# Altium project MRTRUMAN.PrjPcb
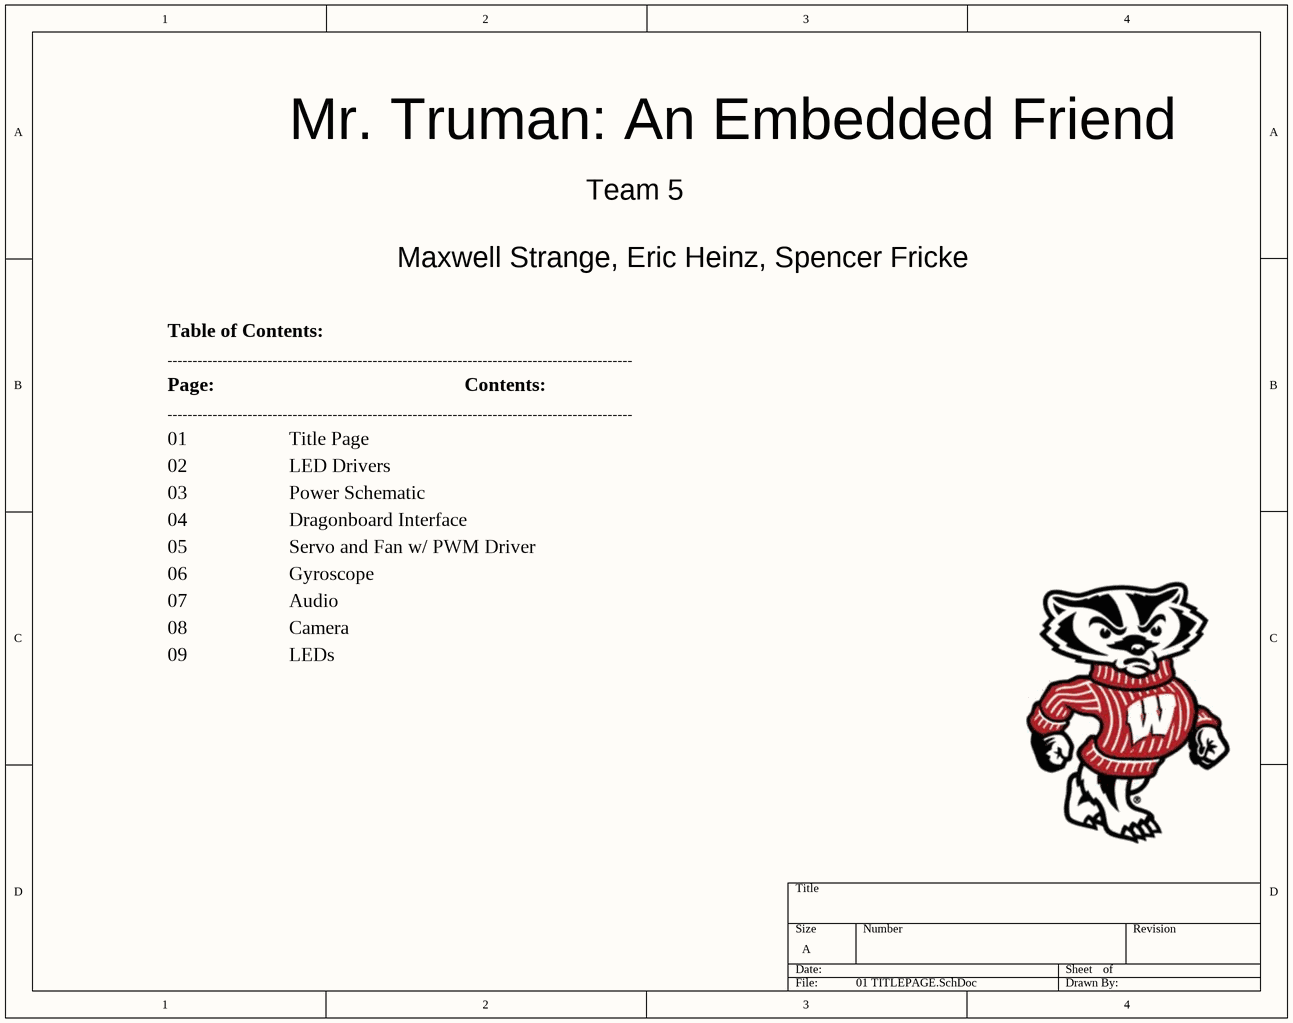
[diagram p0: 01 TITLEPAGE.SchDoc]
9 sheets, 246 parts. Net scope: global (net labels, ports and power ports of the same name join across sheets).
Sheets:
  01 TITLEPAGE.SchDoc
  02 LEDs.SchDoc
  03 POWER.SchDoc
  04 DragonBoard_INTF.SchDoc
  05 SERVO_FAN.SchDoc
  06 Gyro.SchDoc
  07 Audio.SchDoc
  08 Camera.SchDoc
  09 LEDs(2).SchDoc

## Sheet 01 TITLEPAGE.SchDoc: Mr. Truman ECE 453 Project
size A

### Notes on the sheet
- Mr. Truman: An Embedded Friend
- Team 5
- Maxwell Strange, Eric Heinz, Spencer Fricke
- Table of Contents:
- ---------------------------------------------------------------------------------------------
- Page:
- Contents:
- 01
- 02
- 03
- Title Page
- LED Drivers
- Power Schematic
- 04
- 05
- Dragonboard Interface
- Servo and Fan w/ PWM Driver
- 06
- 07
- 08
- Gyroscope
- Audio
- Camera
- 09
- LEDs

## Sheet 02 LEDs.SchDoc
size A
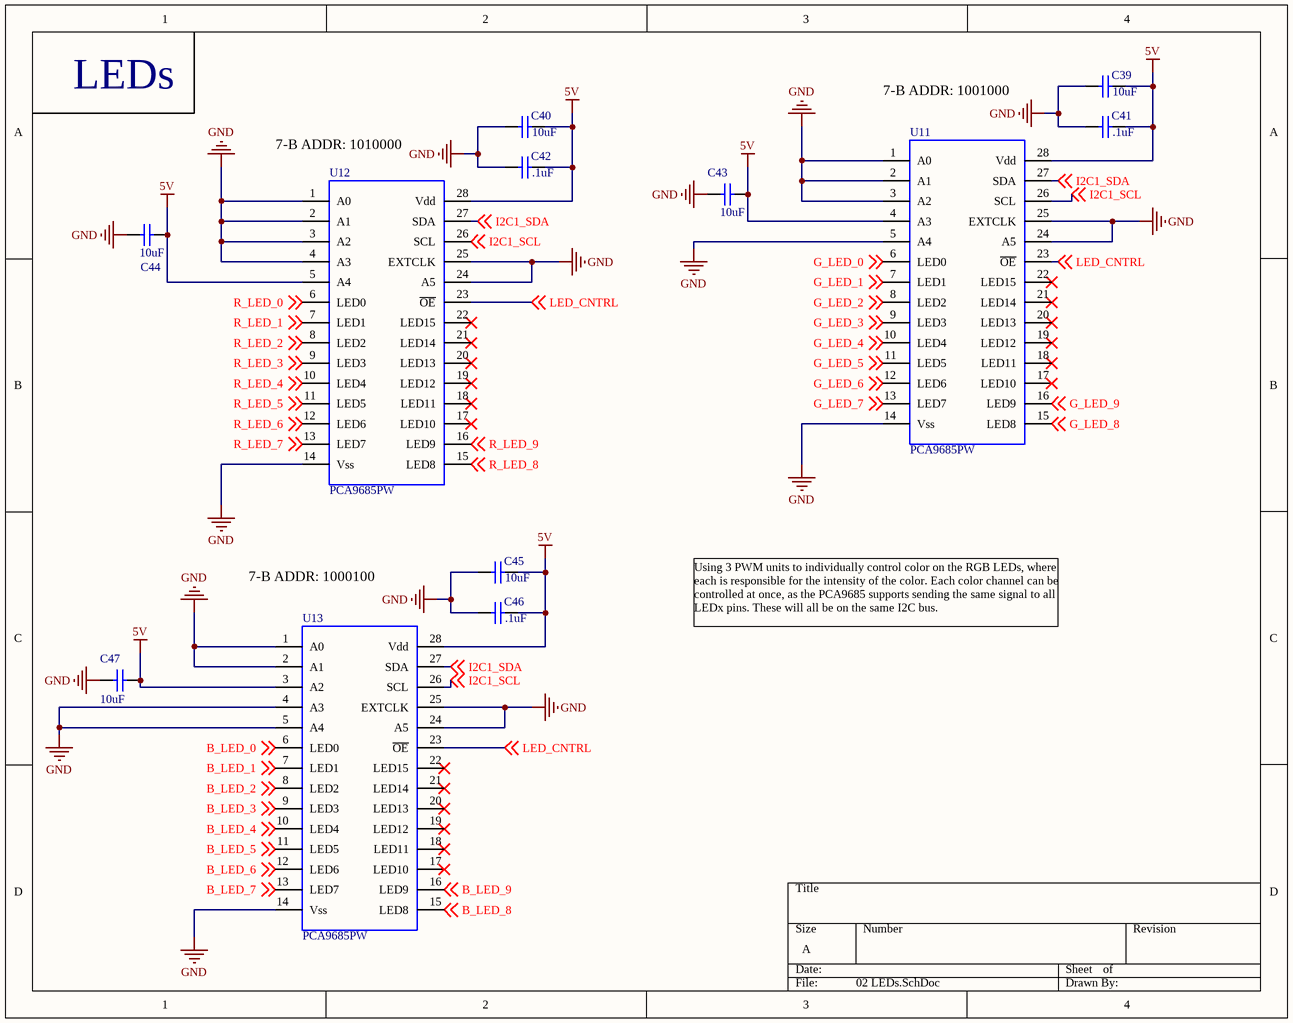
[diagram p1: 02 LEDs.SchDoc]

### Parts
C39  value 10uF  [CAPC2012X135N]  (hidden comment: CAP_0805_10u_16V)
C40  value 10uF  [CAPC2012X135N]  (hidden comment: CAP_0805_10u_16V)
C41  value .1uF  [CAPC2012X135N]  (hidden comment: CAP_0805_.1u_250V)
C42  value .1uF  [CAPC2012X135N]  (hidden comment: CAP_0805_.1u_250V)
C43  value 10uF  [CAPC2012X135N]  (hidden comment: CAP_0805_10u_16V)
C44  value 10uF  [CAPC2012X135N]  (hidden comment: CAP_0805_10u_16V)
C45  value 10uF  [CAPC2012X135N]  (hidden comment: CAP_0805_10u_16V)
C46  value .1uF  [CAPC2012X135N]  (hidden comment: CAP_0805_.1u_250V)
C47  value 10uF  [CAPC2012X135N]  (hidden comment: CAP_0805_10u_16V)
U11  PCA9685PW  [TSSOP28]
U12  PCA9685PW  [TSSOP28]
U13  PCA9685PW  [TSSOP28]

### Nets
5V: C39.2 C40.2 C41.2 C42.2 C43.2 C44.2 C45.2 C46.2 C47.2 U11.4(A3) U11.28(Vdd) U12.5(A4) U12.28(Vdd) U13.3(A2) U13.28(Vdd)
GND: C39.1 C40.1 C41.1 C42.1 C43.1 C44.1 C45.1 C46.1 C47.1 U11.1(A0) U11.2(A1) U11.3(A2) U11.5(A4) U11.14(Vss) U11.24(A5) U11.25(EXTCLK) U12.1(A0) U12.2(A1) U12.3(A2) U12.4(A3) U12.14(Vss) U12.24(A5) U12.25(EXTCLK) U13.1(A0) U13.2(A1) U13.4(A3) U13.5(A4) U13.14(Vss) U13.24(A5) U13.25(EXTCLK)
B_LED_0: U13.6(LED0) ; off-sheet B_LED_0
B_LED_1: U13.7(LED1) ; off-sheet B_LED_1
B_LED_2: U13.8(LED2) ; off-sheet B_LED_2
B_LED_3: U13.9(LED3) ; off-sheet B_LED_3
B_LED_4: U13.10(LED4) ; off-sheet B_LED_4
B_LED_5: U13.11(LED5) ; off-sheet B_LED_5
B_LED_6: U13.12(LED6) ; off-sheet B_LED_6
B_LED_7: U13.13(LED7) ; off-sheet B_LED_7
B_LED_8: U13.15(LED8) ; off-sheet B_LED_8
B_LED_9: U13.16(LED9) ; off-sheet B_LED_9
G_LED_0: U11.6(LED0) ; off-sheet G_LED_0
G_LED_1: U11.7(LED1) ; off-sheet G_LED_1
G_LED_2: U11.8(LED2) ; off-sheet G_LED_2
G_LED_3: U11.9(LED3) ; off-sheet G_LED_3
G_LED_4: U11.10(LED4) ; off-sheet G_LED_4
G_LED_5: U11.11(LED5) ; off-sheet G_LED_5
G_LED_6: U11.12(LED6) ; off-sheet G_LED_6
G_LED_7: U11.13(LED7) ; off-sheet G_LED_7
G_LED_8: U11.15(LED8) ; off-sheet G_LED_8
G_LED_9: U11.16(LED9) ; off-sheet G_LED_9
I2C1_SCL: U11.26(SCL) U12.26(SCL) U13.26(SCL) ; off-sheet I2C1_SCL
I2C1_SDA: U11.27(SDA) U12.27(SDA) U13.27(SDA) ; off-sheet I2C1_SDA
LED_CNTRL: U11.23(~{OE}) U12.23(~{OE}) U13.23(~{OE}) ; off-sheet LED_CNTRL
R_LED_0: U12.6(LED0) ; off-sheet R_LED_0
R_LED_1: U12.7(LED1) ; off-sheet R_LED_1
R_LED_2: U12.8(LED2) ; off-sheet R_LED_2
R_LED_3: U12.9(LED3) ; off-sheet R_LED_3
R_LED_4: U12.10(LED4) ; off-sheet R_LED_4
R_LED_5: U12.11(LED5) ; off-sheet R_LED_5
R_LED_6: U12.12(LED6) ; off-sheet R_LED_6
R_LED_7: U12.13(LED7) ; off-sheet R_LED_7
R_LED_8: U12.15(LED8) ; off-sheet R_LED_8
R_LED_9: U12.16(LED9) ; off-sheet R_LED_9

Not connected (* = marked no-connect by the designer): U11 17(LED10)* 18(LED11)* 19(LED12)* 20(LED13)* 21(LED14)* 22(LED15)*; U12 17(LED10)* 18(LED11)* 19(LED12)* 20(LED13)* 21(LED14)* 22(LED15)*; U13 17(LED10)* 18(LED11)* 19(LED12)* 20(LED13)* 21(LED14)* 22(LED15)*

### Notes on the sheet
- LEDs
- 7-B ADDR: 1001000
- (near U12) 7-B ADDR: 1010000
- 7-B ADDR: 1000100
- Using 3 PWM units to individually control color on the RGB LEDs, where each is responsible for the intensity of the color. Each color channel can be controlled at once, as the PCA9685 supports sending the same signal to all LEDx pins. These will all be on the same I2C bus.

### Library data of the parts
C39 C40 C43-C45 C47 = CAP_0805_10u_16V: Cap Ceramic 10uF 16V X5R 10% SMD 0805 85C T/R; Manufacturer: Johanson Dielectrics; Manufacturer Part Number: 160R15X106KV4E
C41 C42 C46 = CAP_0805_.1u_250V: Cap Ceramic 0.1uF 250V X7T 10% SMD 0805 125C Plastic T/R; Manufacturer: TDK; Manufacturer Part Number: C2012X7T2E104K125AE; Capacitance: 100nF
U11-U13 = PCA9685PW: IC LED DRIVER RGBA 28-TSSOP; Manufacturer: NXP Semiconductors; Manufacturer Part Number: PCA9685PW,118; Number of Outputs: 16; Frequency: 1MHz; Max Supply Voltage: 5.5V; Min Supply Voltage: 2.3V; Nominal Supply Current: 10A; Output Current per Channel: 25mA; High Level Output Current: 10mA; Low Level Output Current: 400A; Power Dissipation: 400W

## Sheet 03 POWER.SchDoc
size 381 x 228 mm
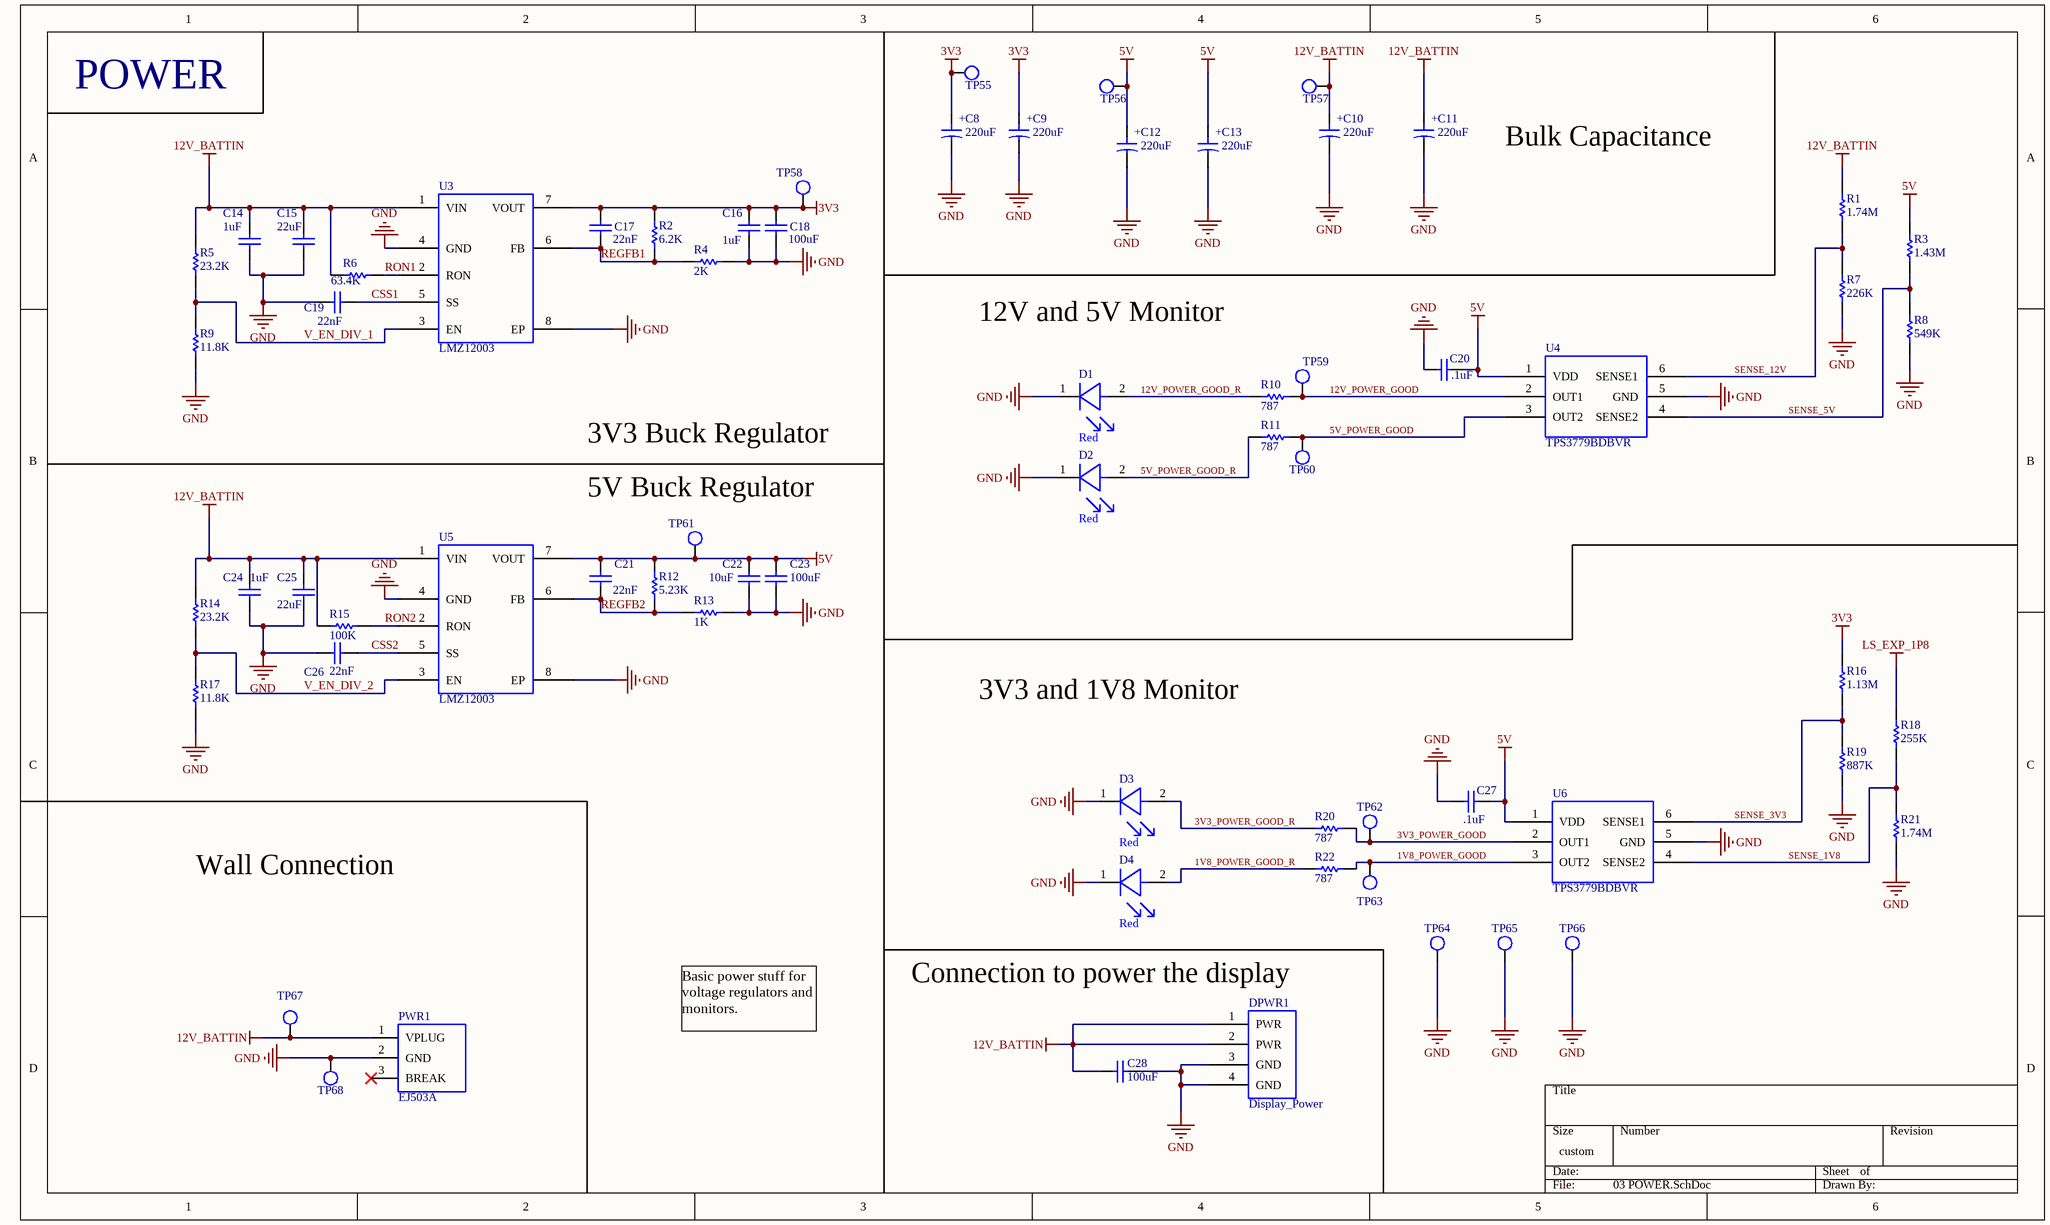
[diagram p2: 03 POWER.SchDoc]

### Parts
C8  Capacitance: 220uF  [CAP_RADIAL]  (hidden comment: CAP ALUM 220UF 20% 25V SMD)
C9  Capacitance: 220uF  [CAP_RADIAL]  (hidden comment: CAP ALUM 220UF 20% 25V SMD)
C10  Capacitance: 220uF  [CAP_RADIAL]  (hidden comment: CAP ALUM 220UF 20% 25V SMD)
C11  Capacitance: 220uF  [CAP_RADIAL]  (hidden comment: CAP ALUM 220UF 20% 25V SMD)
C12  Capacitance: 220uF  [CAP_RADIAL]  (hidden comment: CAP ALUM 220UF 20% 25V SMD)
C13  Capacitance: 220uF  [CAP_RADIAL]  (hidden comment: CAP ALUM 220UF 20% 25V SMD)
C14  value 1uF  [CAPC2012X135N]  (hidden comment: CAP_0805_1u_100V)
C15  value 22uF  [CAPC2012X135N]  (hidden comment: CAP_0805_22u_25V)
C16  value 1uF  [CAPC2012X135N]  (hidden comment: CAP_0805_1u_100V)
C17  value 22nF  [CAPC2012X135N]  (hidden comment: CAP_0805_m22n)
C18  value 100uF  [FP_1210]  (hidden comment: CAP_1210_100u_10V)
C19  value 22nF  [CAPC2012X135N]  (hidden comment: CAP_0805_m22n)
C20  value .1uF  [CAPC2012X135N]  (hidden comment: CAP_0805_.1u_250V)
C21  value 22nF  [CAPC2012X135N]  (hidden comment: CAP_0805_m22n)
C22  value 10uF  [CAPC2012X135N]  (hidden comment: CAP_0805_10u_16V)
C23  value 100uF  [FP_1210]  (hidden comment: CAP_1210_100u_10V)
C24  value 1uF  [CAPC2012X135N]  (hidden comment: CAP_0805_1u_100V)
C25  value 22uF  [CAPC2012X135N]  (hidden comment: CAP_0805_22u_25V)
C26  value 22nF  [CAPC2012X135N]  (hidden comment: CAP_0805_m22n)
C27  value .1uF  [CAPC2012X135N]  (hidden comment: CAP_0805_.1u_250V)
C28  value 100uF  [FP_1210]  (hidden comment: CAP_1210_100u_10V)
D1  Color: Red  [POWERLED_FP]  (hidden comment: LED_RED_636nm)
D2  Color: Red  [POWERLED_FP]  (hidden comment: LED_RED_636nm)
D3  Color: Red  [POWERLED_FP]  (hidden comment: LED_RED_636nm)
D4  Color: Red  [POWERLED_FP]  (hidden comment: LED_RED_636nm)
DPWR1  Display_Power  [LCD_POWER_HEADER]
PWR1  EJ503A  [BARRELJACK]
R1  RES_0805_1.74M  [RES0805]  (value not drawn)
R2  RES_6.2K  [RES0805]  (value not drawn)
R3  RES_1.43M  [RES0805]  (value not drawn)
R4  RES_0805_2K  [RES0805]  (value not drawn)
R5  RES_0805_23.2K  [RES0805]  (value not drawn)
R6  RES_63.4K  [RES0805]  (value not drawn)
R7  RES_0805_226K  [RES0805]  (value not drawn)
R8  RES_549K  [RES0805]  (value not drawn)
R9  RES_0805_11.8K  [RES0805]  (value not drawn)
R10  RES_787  [RES0805]  (value not drawn)
R11  RES_787  [RES0805]  (value not drawn)
R12  RES_5.23K  [RES0805]  (value not drawn)
R13  RES_0805_1K  [RES0805]  (value not drawn)
R14  RES_0805_23.2K  [RES0805]  (value not drawn)
R15  RES_0805_100K  [RES0805]  (value not drawn)
R16  RES_1.13M  [RES0805]  (value not drawn)
R17  RES_0805_11.8K  [RES0805]  (value not drawn)
R18  RES_0805_255K  [RES0805]  (value not drawn)
R19  RES_887K  [RES0805]  (value not drawn)
R20  RES_787  [RES0805]  (value not drawn)
R21  RES_0805_1.74M  [RES0805]  (value not drawn)
R22  RES_787  [RES0805]  (value not drawn)
TP55  TP  [TestPoint_1206]  (value not drawn)
TP56  TP  [TestPoint_1206]  (value not drawn)
TP57  TP  [TestPoint_1206]  (value not drawn)
TP58  TP  [TestPoint_1206]  (value not drawn)
TP59  TP  [TestPoint_1206]  (value not drawn)
TP60  TP  [TestPoint_1206]  (value not drawn)
TP61  TP  [TestPoint_1206]  (value not drawn)
TP62  TP  [TestPoint_1206]  (value not drawn)
TP63  TP  [TestPoint_1206]  (value not drawn)
TP64  TP  [TestPoint_1206]  (value not drawn)
TP65  TP  [TestPoint_1206]  (value not drawn)
TP66  TP  [TestPoint_1206]  (value not drawn)
TP67  TP  [TestPoint_1206]  (value not drawn)
TP68  TP  [TestPoint_1206]  (value not drawn)
U3  LMZ12003  [TO-PMOD-7]
U4  TPS3779BDBVR  [DBV (R-PDSO-G6)]
U5  LMZ12003  [TO-PMOD-7]
U6  TPS3779BDBVR  [DBV (R-PDSO-G6)]

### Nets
3V3: C8.1 C9.1 C16.2 C17.2 C18.2 R2.2 R16.2 TP55.1 TP58.1 U3.7(VOUT)
5V: C12.1 C13.1 C20.2 C21.2 C22.2 C23.2 C27.2 R3.2 R12.2 TP56.1 TP61.1 U4.1(VDD) U5.7(VOUT) U6.1(VDD)
12V_BATTIN: C10.1 C11.1 C14.2 C15.2 C24.2 C25.2 C28.1 DPWR1.1(PWR) DPWR1.2(PWR) PWR1.1(VPLUG) R1.2 R5.2 R6.1 R14.2 R15.1 TP57.1 TP67.1 U3.1(VIN) U5.1(VIN)
GND: C8.2 C9.2 C10.2 C11.2 C12.2 C13.2 C14.1 C15.1 C16.1 C18.1 C19.1 C20.1 C22.1 C23.1 C24.1 C25.1 C26.1 C27.1 C28.2 D1.1(Cathode) D2.1(Cathode) D3.1(Cathode) D4.1(Cathode) DPWR1.3(GND) DPWR1.4(GND) PWR1.2(GND) R4.2 R7.1 R8.1 R9.1 R13.2 R17.1 R19.1 R21.1 TP64.1 TP65.1 TP66.1 TP68.1 U3.4(GND) U3.8(EP) U4.5(GND) U5.4(GND) U5.8(EP) U6.5(GND)
LS_EXP_1P8: R18.2
1V8_POWER_GOOD: R22.1 TP63.1 U6.3(OUT2)
1V8_POWER_GOOD_R: D4.2(Anode) R22.2
3V3_POWER_GOOD: R20.1 TP62.1 U6.2(OUT1)
3V3_POWER_GOOD_R: D3.2(Anode) R20.2
5V_POWER_GOOD: R11.2 TP60.1 U4.3(OUT2)
5V_POWER_GOOD_R: D2.2(Anode) R11.1
12V_POWER_GOOD: R10.2 TP59.1 U4.2(OUT1)
12V_POWER_GOOD_R: D1.2(Anode) R10.1
CSS1: C19.2 U3.5(SS)
CSS2: C26.2 U5.5(SS)
REGFB1: C17.1 R2.1 R4.1 U3.6(FB)
REGFB2: C21.1 R12.1 R13.1 U5.6(FB)
RON1: R6.2 U3.2(RON)
RON2: R15.2 U5.2(RON)
SENSE_1V8: R18.1 R21.2 U6.4(SENSE2)
SENSE_3V3: R16.1 R19.2 U6.6(SENSE1)
SENSE_5V: R3.1 R8.2 U4.4(SENSE2)
SENSE_12V: R1.1 R7.2 U4.6(SENSE1)
V_EN_DIV_1: R5.1 R9.2 U3.3(EN)
V_EN_DIV_2: R14.1 R17.2 U5.3(EN)

Not connected (* = marked no-connect by the designer): PWR1 3(BREAK)*

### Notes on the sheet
- POWER
- Bulk Capacitance
- 12V and 5V Monitor
- 3V3 Buck Regulator
- (near TP61) 5V Buck Regulator
- 3V3 and 1V8 Monitor
- Wall Connection
- Basic power stuff for voltage regulators and monitors.
- (near DPWR1) Connection to power the display

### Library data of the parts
C8-C13 = CAP_RAD_220u_25V: Manufacturer: Nichicon; Manufacturer Part Number: UWT1E221MNL1GS; Dielectric Material: Aluminium; Ripple Current: 155mA; Leakage Current: 3uA; Life (Hours): 1000Hour; Dissipation Factor: 0.16%
C14 C16 C24 = CAP_0805_1u_100V: CAP CER 1UF 100V X7S 0805; Manufacturer: TDK; Manufacturer Part Number: C2012X7S2A105K125AE; Tolerance: 10%
C15 C25 = CAP_0805_22u_25V: 22µF ±20% 25V X5R Ceramic Capacitor -55°C ~ 85°C Surface Mount, MLCC 0805 (2012 Metric) 0.079" L x 0.049" W (2.00mm x 1.25mm); Manufacturer: Samsung; Manufacturer Part Number: CL21A226MAQNNNE
C17 C19 C21 C26 = CAP_0805_22n_100V: CAP CER 0.022UF 100V X7R 0805; Manufacturer: TDK; Manufacturer Part Number: CGJ4J2X7R2A223K125AA; Tolerance: 10%
C18 C23 C28 = CAP_1210_100u_10V: Cap Ceramic 100uF 10V X5R 20% SMD 1210 85C Embossed T/R; Manufacturer: Murata; Manufacturer Part Number: GRM32ER61A107ME20L; Dissipation Factor: 0.035%
C20 C27 = CAP_0805_.1u_250V: as C41 on sheet 02 LEDs
C22 = CAP_0805_10u_16V: as C39 on sheet 02 LEDs
D1-D4 = LED_RED_636nm: Standard LEDs - SMD Surface Mount LEDs; Manufacturer: Lumex; Manufacturer Part Number: SML-LXR85SIC-TR; Lens Colour: Colorless; Viewing Angle: 160°; Forward Current: 20mA; Forward Voltage: 2V; Power Rating: 80mW; Luminous Intensity: 70mcd; Lens Transparency: Clear; Wavelength: 636nm
DPWR1 = Display_Power: 4 Position Thru Hole Connection; Manufacturer: N/A - Just Thru Hole Vias
PWR1 = EJ503A: DC Barrel Jack 2.1mm x 5.5mm 12V 5A; Manufacturer: Memory Protection Devices
R1 R21 = RES_0805_1.74M: RES SMD 1.74M OHM 1% 1/8W 0805; Manufacturer: Yageo; Manufacturer Part Number: RC0805FR-071M74L; Resistance: 1.74MR; Power Rating: 125mW; Voltage Rating: 150V; Temperature Coefficient: 100ppm/°C
R2 = RES_0805_6.2K: Yageo RC0805 Series Thick Film Surface Mount Resistor 0805 Case 6.2k 1% 0.125W 100ppm/C; Manufacturer Part Number: RC0805FR-076K2L; Power Rating: 125mW; Resistance: 6.2KR; Temperature Coefficient: 100ppm/°C; Voltage Rating (DC): 150V
R3 = RES_0805_1.43M: RES SMD 1.43M OHM 1% 1/8W 0805; Manufacturer: Yageo; Manufacturer Part Number: RC0805FR-071M43L; Voltage Rating: 150V; Resistance: 1.43MR; Power Rating: 125mW; Temperature Coefficient: 100ppm/°C
R4 = RES_0805_2K: RES SMD 2K OHM 5% 1/8W 0805; Manufacturer: Yageo; Manufacturer Part Number: RC0805JR-072KL; Resistance: 2KR; Power Rating: 125mW; Voltage Rating: 150V; Temperature Coefficient: 100ppm/°C
R5 R14 = RES_0805_23.2K: RESISTOR, THICK FILM, 23.2KOHM, 125mW, ± 1%; Manufacturer: Panasonic ECG; Manufacturer Part Number: ERJ-6ENF2322V; Resistance: 23.2KR; Voltage Rating: 150V; Temperature Coefficient: 100ppm/°C
R6 = RES_0805_63.4K: RES SMD 63.4K OHM 1% 1/8W 0805; Manufacturer: Yageo; Manufacturer Part Number: RC0805FR-0763K4L; Resistance: 63.4KR; Power Rating: 125mW; Voltage Rating: 150V; Temperature Coefficient: 100ppm/°C
R7 = RES_0805_226K: Res Thick Film 0805 226K Ohm 1% 1/8W ±100ppm/C Molded SMD Punched Carrier T/R; Manufacturer: Panasonic ECG; Manufacturer Part Number: ERJ-6ENF2263V; Resistance: 226KR; Power Rating: 125mW; Voltage Rating: 150V; Temperature Coefficient: 100ppm/°C
R8 = RES_0805_549K: RES SMD 549K OHM 1% 1/8W 0805; Manufacturer: Vishay; Manufacturer Part Number: CRCW0805549KFKEA; Resistance: 549KR; Power Rating: 125mW; Voltage Rating: 150V; Temperature Coefficient: 100ppm/°C
R9 R17 = RES_0805_11.8K: RES SMD 11.8K OHM 1% 1/8W 0805; Manufacturer: Yageo; Manufacturer Part Number: RC0805FR-0711K8L; Resistance: 11.8KR; Temperature Coefficient: 100ppm/°C; Voltage Rating (DC): 150V; Power Rating: 125mW
R10 R11 R20 R22 = RES_0805_787: RES SMD 787 OHM 1% 1/8W 0805; Manufacturer: Yageo; Manufacturer Part Number: RC0805FR-07787RL; Resistance: 787R; Max Power Dissipation: 125mW; Temperature Coefficient: 100ppm/°C; Voltage Rating (DC): 150V
R12 = RES_0805_5.23K: Thick Film Resistors 5.23K OHM 1%; Manufacturer: Yageo; Manufacturer Part Number: RC0805FR-075K23L; Resistance: 5.23KR; Power Rating: 125mW; Voltage Rating: 150V; Temperature Coefficient: 100ppm/°C
R13 = RES_0805_1K: RES SMD 1K OHM 1% 1/8W 0805; Manufacturer: Yageo; Manufacturer Part Number: RC0805FR-071KL; Resistance: 1KR; Temperature Coefficient: 100ppm/°C; Voltage Rating (DC): 150V; Power Rating: 125mW
R15 = RES_0805_100K: Res Thick Film 0805 100K Ohm 1% 0.125W(1/8W) ±100ppm/C Molded SMD Automotive Punched T/R; Manufacturer: Panasonic ECG; Manufacturer Part Number: ERJ-6ENF1003V; Resistance: 100KR; Power Rating: 125mW; Temperature Coefficient: 100ppm/°C; Voltage Rating (DC): 150V
R16 = RES_0805_1.13M: Res Thick Film 0805 1.13M Ohm 1% 1/8W 100ppm/C Molded SMD Punched Carrier T/R; Manufacturer: Panasonic; Manufacturer Part Number: ERJ-6ENF1134V; Resistance: 1.13MR; Power Rating: 125mW; Voltage Rating: 150V; Temperature Coefficient: 100ppm/°C
R18 = RES_0805_255K: RES SMD 255K OHM 1% 1/8W 0805; Manufacturer: Yageo; Manufacturer Part Number: RC0805FR-07255KL; Power Rating: 125mW; Resistance: 255KR; Voltage Rating: 150V; Temperature Coefficient: 100ppm/°C
R19 = RES_0805_887K: Thick Film Resistors - SMD 887K OHM 1%; Manufacturer: Yageo; Manufacturer Part Number: RC0805FR-07887KL; Voltage Rating (DC): 150V; Power Rating: 125mW; Resistance: 887KR; Temperature Coefficient: 100ppm/°C
TP55-TP68 = TP: Testpoint_1206; Manufacturer: TE Connectivity; Manufacturer Part Number: 1625854-4; Resistance: 0mR
U3 U5 = LMZ12003: POWER MODULE, TO-PMOD-7, FULL REEL; Manufacturer: Texas Instruments; Manufacturer Part Number: LMZ12003TZ-ADJ/NOPB; Min Input Voltage: 4.5V; Max Input Voltage: 20V; Number of Outputs: 1; Output Current: 3A; Output Voltage: 6V; Switching Frequency: 1MHz; Efficiency: 92%; Min Output Voltage: 800mV; Quiescent Current: 1mA; Max Power Dissipation: 18W
U4 U6 = TPS3779BDBVR: Voltage Detector, Active-Low, Push-Pull Reset, 2-Monitors, 1.5V-6.5Vin, SOT-23-6; Manufacturer: Texas Instruments; Manufacturer Part Number: TPS3779BDBVT; Number of Voltages Monitored: 2; Reset: Active Low; Threshold Voltage: 1.194V; Min Supply Voltage: 1.5V; Max Supply Voltage: 6.5V; Quiescent Current: 2uA

## Sheet 04 DragonBoard_INTF.SchDoc
size 457 x 241 mm
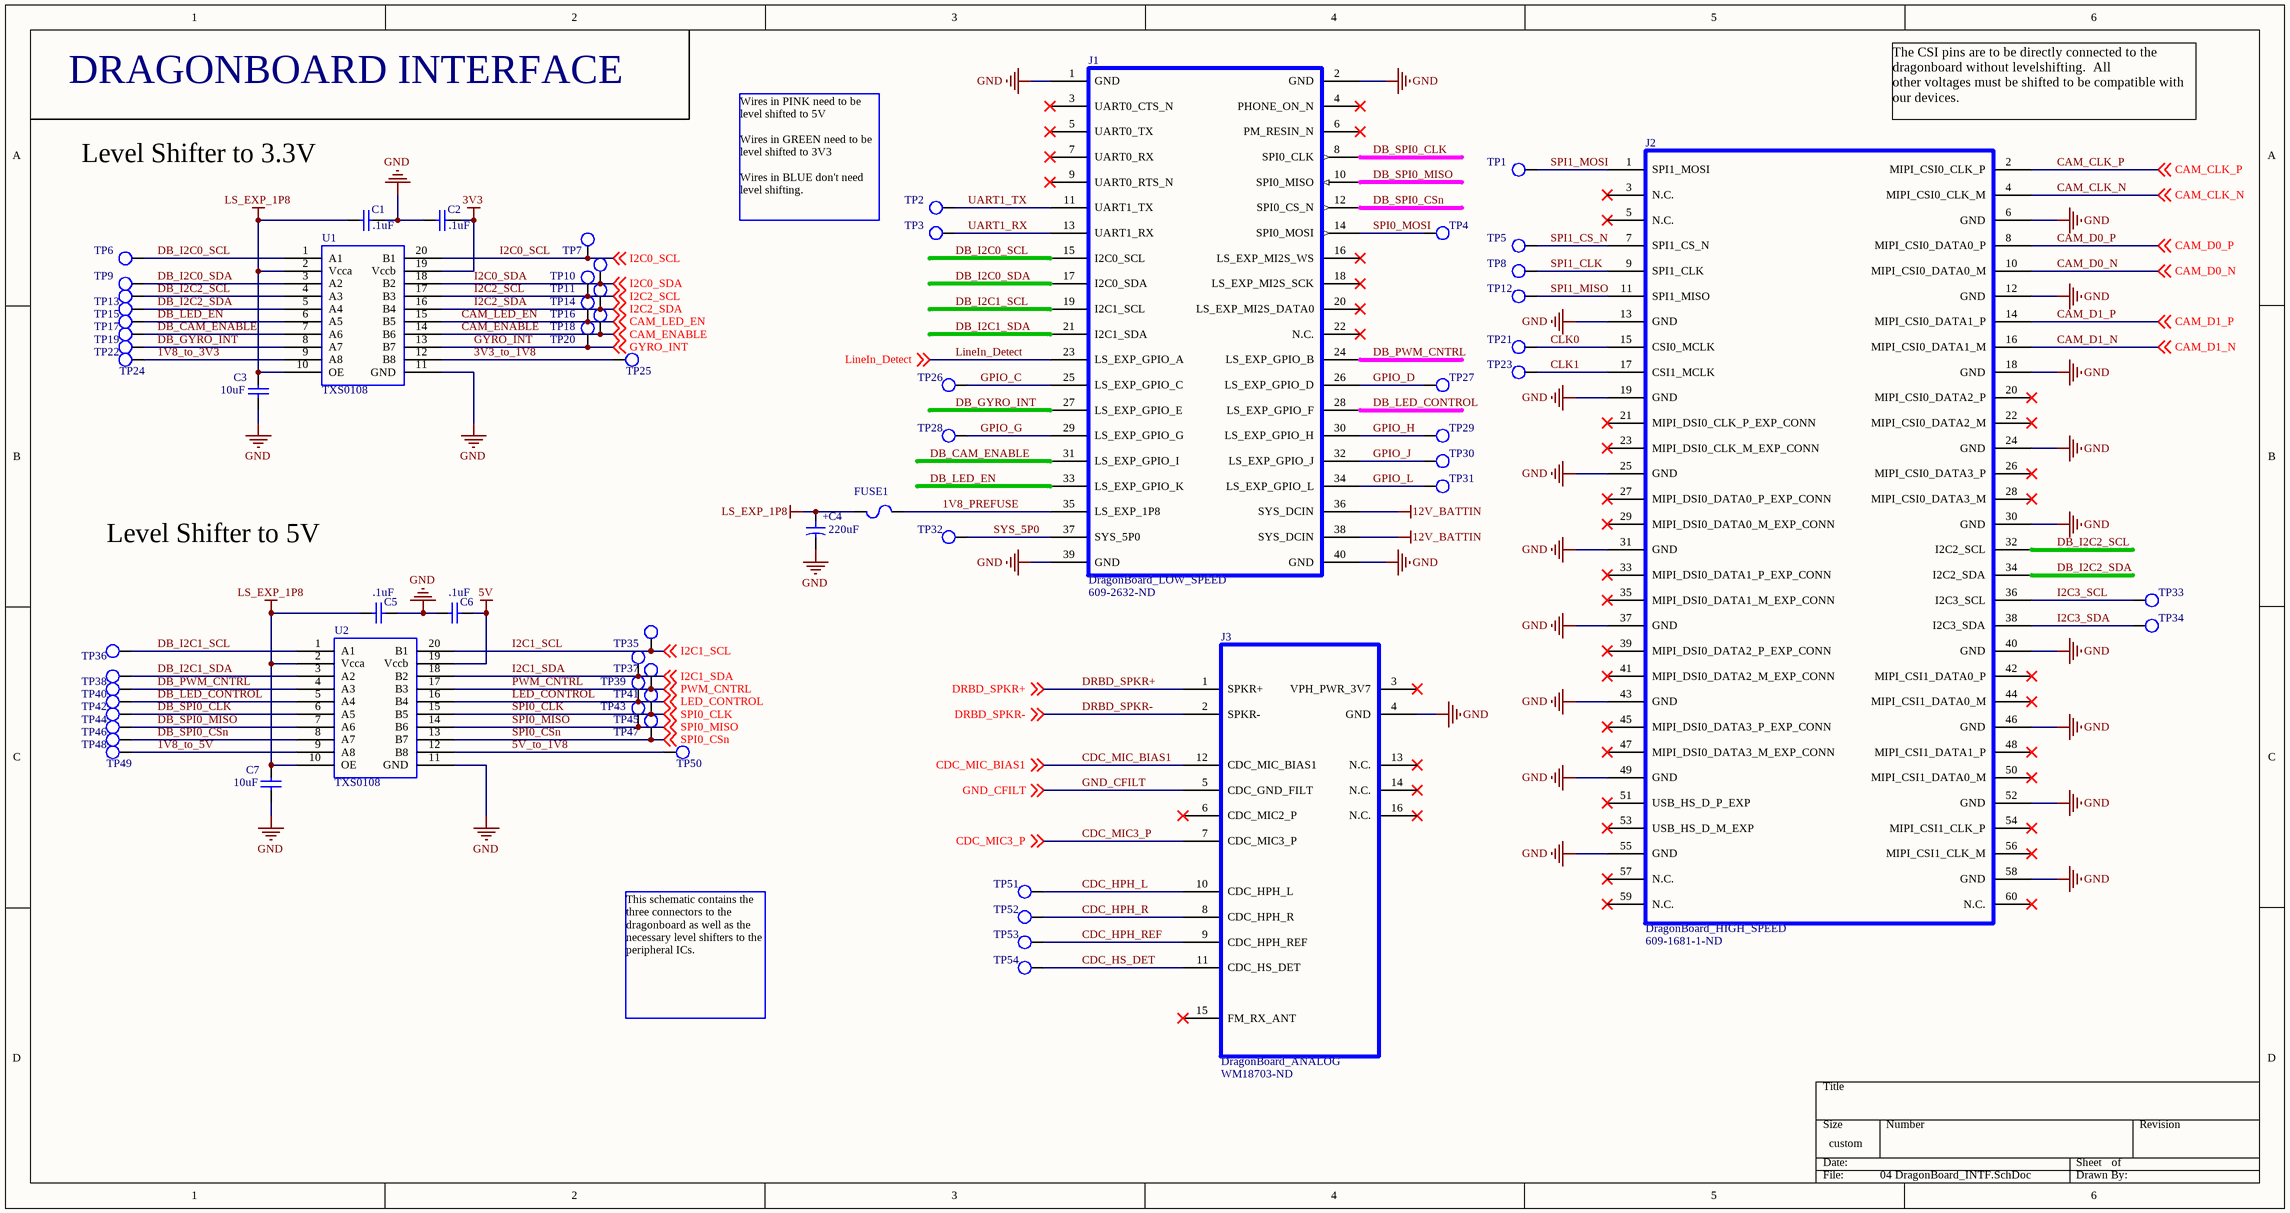
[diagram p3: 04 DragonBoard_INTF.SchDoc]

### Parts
C1  value .1uF  [CAPC2012X135N]  (hidden comment: CAP_0805_.1u_250V)
C2  value .1uF  [CAPC2012X135N]  (hidden comment: CAP_0805_.1u_250V)
C3  value 10uF  [CAPC2012X135N]  (hidden comment: CAP_0805_10u_16V)
C4  Capacitance: 220uF  [CAP_RADIAL]  (hidden comment: CAP ALUM 220UF 20% 25V SMD)
C5  value .1uF  [CAPC2012X135N]  (hidden comment: CAP_0805_.1u_250V)
C6  value .1uF  [CAPC2012X135N]  (hidden comment: CAP_0805_.1u_250V)
C7  value 10uF  [CAPC2012X135N]  (hidden comment: CAP_0805_10u_16V)
FUSE1  FUSE_0805_1A_32VDC  [RES0805]  (value not drawn)
J1  DragonBoard_LOW_SPEED  Supplier Part Number 1: 609-2632-ND  [57202_40_PIN_HEADER]
J2  DragonBoard_HIGH_SPEED  Supplier Part Number 1: 609-1681-1-ND  [DB_HIGH_SPEED]
J3  DragonBoard_ANALOG  Supplier Part Number 1: WM18703-ND  [16_PIN_ANALOG_CONN]
TP1  TP  [TestPoint_1206]  (value not drawn)
TP2  TP  [TestPoint_1206]  (value not drawn)
TP3  TP  [TestPoint_1206]  (value not drawn)
TP4  TP  [TestPoint_1206]  (value not drawn)
TP5  TP  [TestPoint_1206]  (value not drawn)
TP6  TP  [TestPoint_1206]  (value not drawn)
TP7  TP  [TestPoint_1206]  (value not drawn)
TP8  TP  [TestPoint_1206]  (value not drawn)
TP9  TP  [TestPoint_1206]  (value not drawn)
TP10  TP  [TestPoint_1206]  (value not drawn)
TP11  TP  [TestPoint_1206]  (value not drawn)
TP12  TP  [TestPoint_1206]  (value not drawn)
TP13  TP  [TestPoint_1206]  (value not drawn)
TP14  TP  [TestPoint_1206]  (value not drawn)
TP15  TP  [TestPoint_1206]  (value not drawn)
TP16  TP  [TestPoint_1206]  (value not drawn)
TP17  TP  [TestPoint_1206]  (value not drawn)
TP18  TP  [TestPoint_1206]  (value not drawn)
TP19  TP  [TestPoint_1206]  (value not drawn)
TP20  TP  [TestPoint_1206]  (value not drawn)
TP21  TP  [TestPoint_1206]  (value not drawn)
TP22  TP  [TestPoint_1206]  (value not drawn)
TP23  TP  [TestPoint_1206]  (value not drawn)
TP24  TP  [TestPoint_1206]  (value not drawn)
TP25  TP  [TestPoint_1206]  (value not drawn)
TP26  TP  [TestPoint_1206]  (value not drawn)
TP27  TP  [TestPoint_1206]  (value not drawn)
TP28  TP  [TestPoint_1206]  (value not drawn)
TP29  TP  [TestPoint_1206]  (value not drawn)
TP30  TP  [TestPoint_1206]  (value not drawn)
TP31  TP  [TestPoint_1206]  (value not drawn)
TP32  TP  [TestPoint_1206]  (value not drawn)
TP33  TP  [TestPoint_1206]  (value not drawn)
TP34  TP  [TestPoint_1206]  (value not drawn)
TP35  TP  [TestPoint_1206]  (value not drawn)
TP36  TP  [TestPoint_1206]  (value not drawn)
TP37  TP  [TestPoint_1206]  (value not drawn)
TP38  TP  [TestPoint_1206]  (value not drawn)
TP39  TP  [TestPoint_1206]  (value not drawn)
TP40  TP  [TestPoint_1206]  (value not drawn)
TP41  TP  [TestPoint_1206]  (value not drawn)
TP42  TP  [TestPoint_1206]  (value not drawn)
TP43  TP  [TestPoint_1206]  (value not drawn)
TP44  TP  [TestPoint_1206]  (value not drawn)
TP45  TP  [TestPoint_1206]  (value not drawn)
TP46  TP  [TestPoint_1206]  (value not drawn)
TP47  TP  [TestPoint_1206]  (value not drawn)
TP48  TP  [TestPoint_1206]  (value not drawn)
TP49  TP  [TestPoint_1206]  (value not drawn)
TP50  TP  [TestPoint_1206]  (value not drawn)
TP51  TP  [TestPoint_1206]  (value not drawn)
TP52  TP  [TestPoint_1206]  (value not drawn)
TP53  TP  [TestPoint_1206]  (value not drawn)
TP54  TP  [TestPoint_1206]  (value not drawn)
U1  TXS0108  [TSSOP20]
U2  TXS0108  [TSSOP20]

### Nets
3V3: C2.2 U1.19(Vccb)
5V: C6.2 U2.19(Vccb)
12V_BATTIN: J1.36(SYS_DCIN) J1.38(SYS_DCIN)
GND: C1.2 C2.1 C3.1 C4.2 C5.2 C6.1 C7.1 J1.1(GND) J1.2(GND) J1.39(GND) J1.40(GND) J2.6(GND) J2.12(GND) J2.13(GND) J2.18(GND) J2.19(GND) J2.24(GND) J2.25(GND) J2.30(GND) J2.31(GND) J2.37(GND) J2.40(GND) J2.43(GND) J2.46(GND) J2.49(GND) J2.52(GND) J2.55(GND) J2.58(GND) J3.4(GND) U1.11(GND) U2.11(GND)
LS_EXP_1P8: C1.1 C3.2 C4.1 C5.1 C7.2 FUSE1.1 U1.2(Vcca) U1.10(OE) U2.2(Vcca) U2.10(OE)
1V8_PREFUSE: FUSE1.2 J1.35(LS_EXP_1P8)
1V8_to_3V3: TP24.1 U1.9(A8)
1V8_to_5V: TP49.1 U2.9(A8)
3V3_to_1V8: TP25.1 U1.12(B8)
5V_to_1V8: TP50.1 U2.12(B8)
CAM_CLK_N: J2.4(MIPI_CSI0_CLK_M) ; off-sheet CAM_CLK_N
CAM_CLK_P: J2.2(MIPI_CSI0_CLK_P) ; off-sheet CAM_CLK_P
CAM_D0_N: J2.10(MIPI_CSI0_DATA0_M) ; off-sheet CAM_D0_N
CAM_D0_P: J2.8(MIPI_CSI0_DATA0_P) ; off-sheet CAM_D0_P
CAM_D1_N: J2.16(MIPI_CSI0_DATA1_M) ; off-sheet CAM_D1_N
CAM_D1_P: J2.14(MIPI_CSI0_DATA1_P) ; off-sheet CAM_D1_P
CAM_ENABLE: TP18.1 U1.14(B6) ; off-sheet CAM_ENABLE
CAM_LED_EN: TP16.1 U1.15(B5) ; off-sheet CAM_LED_EN
CDC_HPH_L: J3.10(CDC_HPH_L) TP51.1
CDC_HPH_R: J3.8(CDC_HPH_R) TP52.1
CDC_HPH_REF: J3.9(CDC_HPH_REF) TP53.1
CDC_HS_DET: J3.11(CDC_HS_DET) TP54.1
CDC_MIC3_P: J3.7(CDC_MIC3_P) ; off-sheet CDC_MIC3_P
CDC_MIC_BIAS1: J3.12(CDC_MIC_BIAS1) ; off-sheet CDC_MIC_BIAS1
CLK0: J2.15(CSI0_MCLK) TP21.1
CLK1: J2.17(CSI1_MCLK) TP23.1
DB_CAM_ENABLE: J1.31(LS_EXP_GPIO_I) TP19.1 U1.7(A6)
DB_GYRO_INT: J1.27(LS_EXP_GPIO_E) TP22.1 U1.8(A7)
DB_I2C0_SCL: J1.15(I2C0_SCL) TP6.1 U1.1(A1)
DB_I2C0_SDA: J1.17(I2C0_SDA) TP9.1 U1.3(A2)
DB_I2C1_SCL: J1.19(I2C1_SCL) TP36.1 U2.1(A1)
DB_I2C1_SDA: J1.21(I2C1_SDA) TP38.1 U2.3(A2)
DB_I2C2_SCL: J2.32(I2C2_SCL) TP13.1 U1.4(A3)
DB_I2C2_SDA: J2.34(I2C2_SDA) TP15.1 U1.5(A4)
DB_LED_CONTROL: J1.28(LS_EXP_GPIO_F) TP42.1 U2.5(A4)
DB_LED_EN: J1.33(LS_EXP_GPIO_K) TP17.1 U1.6(A5)
DB_PWM_CNTRL: J1.24(LS_EXP_GPIO_B) TP40.1 U2.4(A3)
DB_SPI0_CLK: J1.8(SPI0_CLK) TP44.1 U2.6(A5)
DB_SPI0_CSn: J1.12(SPI0_CS_N) TP48.1 U2.8(A7)
DB_SPI0_MISO: J1.10(SPI0_MISO) TP46.1 U2.7(A6)
DRBD_SPKR+: J3.1(SPKR+) ; off-sheet DRBD_SPKR+
DRBD_SPKR-: J3.2(SPKR-) ; off-sheet DRBD_SPKR-
GND_CFILT: J3.5(CDC_GND_FILT) ; off-sheet GND_CFILT
GPIO_C: J1.25(LS_EXP_GPIO_C) TP26.1
GPIO_D: J1.26(LS_EXP_GPIO_D) TP27.1
GPIO_G: J1.29(LS_EXP_GPIO_G) TP28.1
GPIO_H: J1.30(LS_EXP_GPIO_H) TP29.1
GPIO_J: J1.32(LS_EXP_GPIO_J) TP30.1
GPIO_L: J1.34(LS_EXP_GPIO_L) TP31.1
GYRO_INT: TP20.1 U1.13(B7) ; off-sheet GYRO_INT
I2C0_SCL: TP7.1 U1.20(B1) ; off-sheet I2C0_SCL
I2C0_SDA: TP10.1 U1.18(B2) ; off-sheet I2C0_SDA
I2C1_SCL: TP35.1 U2.20(B1) ; off-sheet I2C1_SCL
I2C1_SDA: TP37.1 U2.18(B2) ; off-sheet I2C1_SDA
I2C2_SCL: TP11.1 U1.17(B3) ; off-sheet I2C2_SCL
I2C2_SDA: TP14.1 U1.16(B4) ; off-sheet I2C2_SDA
I2C3_SCL: J2.36(I2C3_SCL) TP33.1
I2C3_SDA: J2.38(I2C3_SDA) TP34.1
LED_CONTROL: TP41.1 U2.16(B4) ; off-sheet LED_CONTROL
LineIn_Detect: J1.23(LS_EXP_GPIO_A) ; off-sheet LineIn_Detect
PWM_CNTRL: TP39.1 U2.17(B3) ; off-sheet PWM_CNTRL
SPI0_CLK: TP43.1 U2.15(B5) ; off-sheet SPI0_CLK
SPI0_CSn: TP47.1 U2.13(B7) ; off-sheet SPI0_CSn
SPI0_MISO: TP45.1 U2.14(B6) ; off-sheet SPI0_MISO
SPI0_MOSI: J1.14(SPI0_MOSI) TP4.1
SPI1_CLK: J2.9(SPI1_CLK) TP8.1
SPI1_CS_N: J2.7(SPI1_CS_N) TP5.1
SPI1_MISO: J2.11(SPI1_MISO) TP12.1
SPI1_MOSI: J2.1(SPI1_MOSI) TP1.1
SYS_5P0: J1.37(SYS_5P0) TP32.1
UART1_RX: J1.13(UART1_RX) TP3.1
UART1_TX: J1.11(UART1_TX) TP2.1

Not connected (* = marked no-connect by the designer): J1 3(UART0_CTS_N)* 4(PHONE_ON_N)* 5(UART0_TX)* 6(PM_RESIN_N)* 7(UART0_RX)* 9(UART0_RTS_N)* 16(LS_EXP_MI2S_WS)* 18(LS_EXP_MI2S_SCK)* 20(LS_EXP_MI2S_DATA0)* 22(N.C.)*; J2 3(N.C.)* 5(N.C.)* 20(MIPI_CSI0_DATA2_P)* 21(MIPI_DSI0_CLK_P_EXP_CONN)* 22(MIPI_CSI0_DATA2_M)* 23(MIPI_DSI0_CLK_M_EXP_CONN)* 26(MIPI_CSI0_DATA3_P)* 27(MIPI_DSI0_DATA0_P_EXP_CONN)* 28(MIPI_CSI0_DATA3_M)* 29(MIPI_DSI0_DATA0_M_EXP_CONN)* 33(MIPI_DSI0_DATA1_P_EXP_CONN)* 35(MIPI_DSI0_DATA1_M_EXP_CONN)* 39(MIPI_DSI0_DATA2_P_EXP_CONN)* 41(MIPI_DSI0_DATA2_M_EXP_CONN)* 42(MIPI_CSI1_DATA0_P)* 44(MIPI_CSI1_DATA0_M)* 45(MIPI_DSI0_DATA3_P_EXP_CONN)* 47(MIPI_DSI0_DATA3_M_EXP_CONN)* 48(MIPI_CSI1_DATA1_P)* 50(MIPI_CSI1_DATA0_M)* 51(USB_HS_D_P_EXP)* 53(USB_HS_D_M_EXP)* 54(MIPI_CSI1_CLK_P)* 56(MIPI_CSI1_CLK_M)* 57(N.C.)* 59(N.C.)* 60(N.C.)*; J3 3(VPH_PWR_3V7)* 6(CDC_MIC2_P)* 13(N.C.)* 14(N.C.)* 15(FM_RX_ANT)* 16(N.C.)*

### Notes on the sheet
- DRAGONBOARD INTERFACE
- The CSI pins are to be directly connected to the dragonboard without levelshifting.  All
  other voltages must be shifted to be compatible with our devices.
- Level Shifter to 3.3V
- Wires in PINK need to be level shifted to 5V
  Wires in GREEN need to be level shifted to 3V3
  Wires in BLUE don't need level shifting.
- Level Shifter to 5V
- This schematic contains the three connectors to the dragonboard as well as the necessary level shifters to the peripheral ICs.

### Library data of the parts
C1 C2 C5 C6 = CAP_0805_.1u_250V: as C41 on sheet 02 LEDs
C3 C7 = CAP_0805_10u_16V: as C39 on sheet 02 LEDs
C4 = CAP_RAD_220u_25V: as C8 on sheet 03 POWER
FUSE1 = FUSE_0805_1A_32VDC: FUSE 1.00A 0805 VFAST SMD; Manufacturer: Vishay; Manufacturer Part Number: MFU0805FF01000P100; Voltage Rating (DC): 32V; Current Rating: 1A; DC Cold Resistance: 185mR; Approvals: UL
J1 = DragonBoard_LOW_SPEED: 40 Positions Header, Unshrouded Connector 0.079" (2.00mm) Surface Mount Gold, GXT™; Manufacturer: Amphenol FCI; Manufacturer Part Number: 57202-G52-20LF; Number of Positions: 40; Insulation Resistance: 1GR; Max Voltage Rating (AC): 650V; Gender: Male; Connector Type: Male Pin; Contact Resistance: 25mR; Current Rating: 2A; Pitch: 2mm; Row Spacing: 0.079inch; Mating Post Length: 4mm
J2 = DragonBoard_HIGH_SPEED: 60 Position Connector Plug, Center Strip Contacts Surface Mount Gold; Manufacturer: Amphenol FCI; Manufacturer Part Number: 61083-064402LF; Contact Resistance: 50mR; Number of Positions: 60; Max Voltage Rating (AC): 100V; Current Rating: 500mA; Gender: Male; Pitch: 0.8mm; Stack Height: 7.7mm
J3 = DragonBoard_ANALOG: Conn Socket Strip RCP 16 POS 2mm Solder ST SMD Tube; Manufacturer: Molex; Manufacturer Part Number: 0791091007; Connector Type: Receptacle,Socket; Number of Positions: 16; Gender: Female; Max Voltage Rating (AC): 125V; Contact Resistance: 25mR; Row Spacing: 0.079inch
TP1-TP54 = TP: as TP55 on sheet 03 POWER
U1 U2 = TXS0108: TRANSLATOR, VOLTAGE, 8BIT, 20TSSOP; Manufacturer: Texas Instruments; Manufacturer Part Number: TXS0108EPWR; Output Current: 620µA; Propagation Delay: 4.8ns; Logic Case Style: TSSOP; No. of Pins: 20; Supply Voltage Min: 1.2V; Logic Type: Voltage Level Translator; Supply Voltage Max: 5.5V; No. of Inputs: 8; SVHC: No SVHC (16-Jun-2014)

## Sheet 05 SERVO_FAN.SchDoc
size A
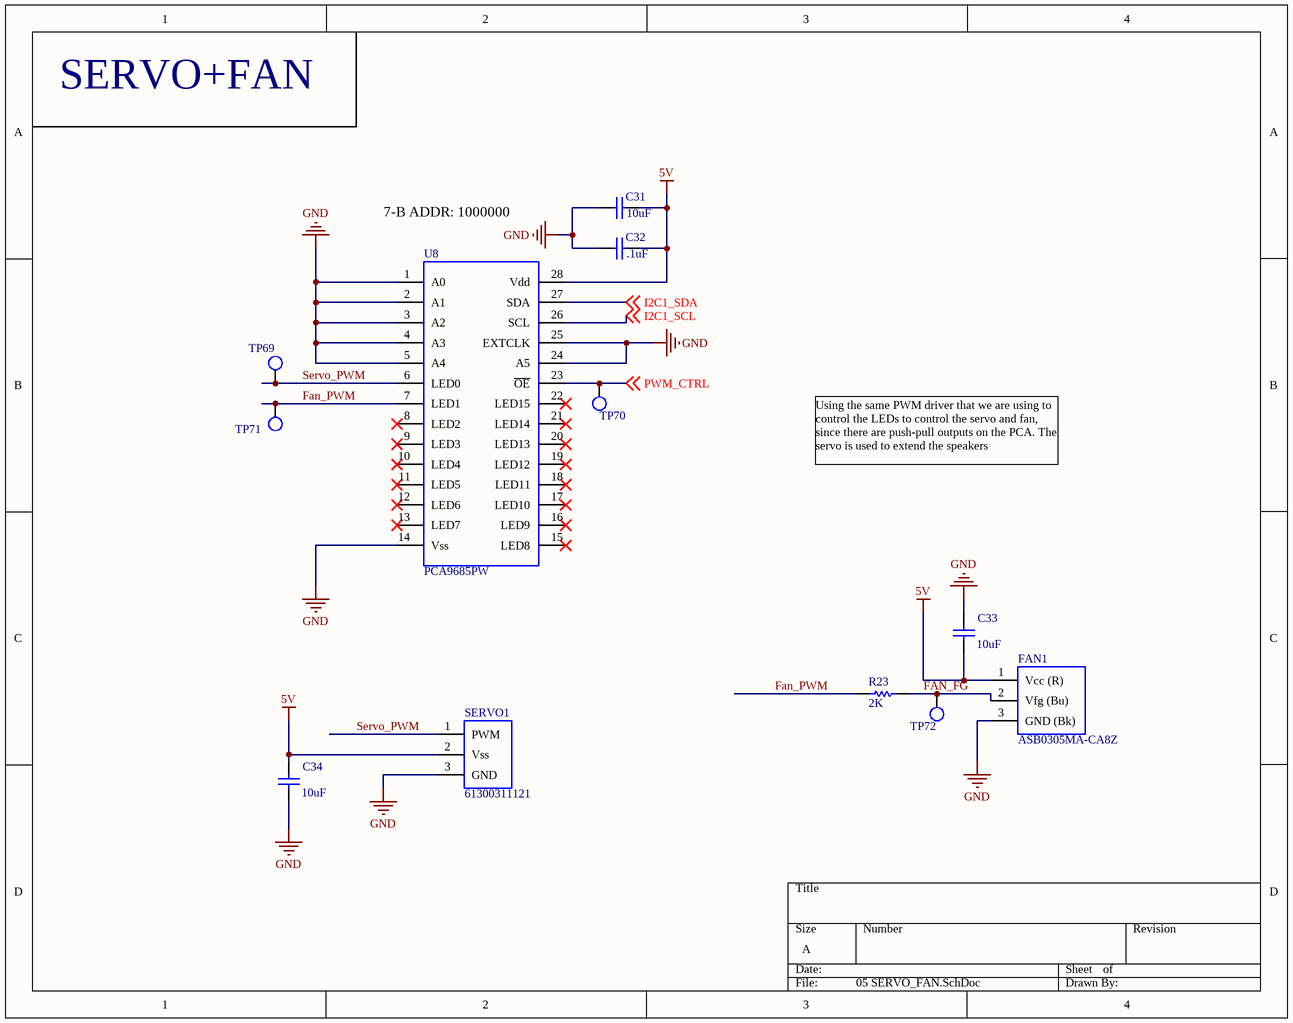
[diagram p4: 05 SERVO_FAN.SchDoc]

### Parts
C31  value 10uF  [CAPC2012X135N]  (hidden comment: CAP_0805_10u_16V)
C32  value .1uF  [CAPC2012X135N]  (hidden comment: CAP_0805_.1u_250V)
C33  value 10uF  [CAPC2012X135N]  (hidden comment: CAP_0805_10u_16V)
C34  value 10uF  [CAPC2012X135N]  (hidden comment: CAP_0805_10u_16V)
FAN1  ASB0305MA-CA8Z  [FAN_HEADER]
R23  RES_0805_2K  [RES0805]  (value not drawn)
SERVO1  61300311121  [SERVO_HEADER]
TP69  TP  [TestPoint_1206]  (value not drawn)
TP70  TP  [TestPoint_1206]  (value not drawn)
TP71  TP  [TestPoint_1206]  (value not drawn)
TP72  TP  [TestPoint_1206]  (value not drawn)
U8  PCA9685PW  [TSSOP28]

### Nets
5V: C31.2 C32.2 C33.1 C34.2 FAN1.1(Vcc_(R)) SERVO1.2(Vss) U8.28(Vdd)
GND: C31.1 C32.1 C33.2 C34.1 FAN1.3(GND_(Bk)) SERVO1.3(GND) U8.1(A0) U8.2(A1) U8.3(A2) U8.4(A3) U8.5(A4) U8.14(Vss) U8.24(A5) U8.25(EXTCLK)
FAN_FG: FAN1.2(Vfg_(Bu)) R23.2 TP72.1
Fan_PWM: R23.1 TP71.1 U8.7(LED1)
I2C1_SCL: U8.26(SCL) ; off-sheet I2C1_SCL
I2C1_SDA: U8.27(SDA) ; off-sheet I2C1_SDA
PWM_CTRL: TP70.1 U8.23(~{OE}) ; off-sheet PWM_CTRL
Servo_PWM: SERVO1.1(PWM) TP69.1 U8.6(LED0)

Not connected (* = marked no-connect by the designer): U8 8(LED2)* 9(LED3)* 10(LED4)* 11(LED5)* 12(LED6)* 13(LED7)* 15(LED8)* 16(LED9)* 17(LED10)* 18(LED11)* 19(LED12)* 20(LED13)* 21(LED14)* 22(LED15)*

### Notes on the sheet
- SERVO+FAN
- 7-B ADDR: 1000000
- Using the same PWM driver that we are using to control the LEDs to control the servo and fan, since there are push-pull outputs on the PCA. The servo is used to extend the speakers

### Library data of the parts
C31 C33 C34 = CAP_0805_10u_16V: as C39 on sheet 02 LEDs
C32 = CAP_0805_.1u_250V: as C41 on sheet 02 LEDs
FAN1 = ASB0305MA-CA8Z: FAN AXIAL 30X10MM 5VDC WIRE; Manufacturer: Delta Design; Airflow: 3.4CFM; Noise: 23dBA; Current Rating: 110mA; Max Power Dissipation: 550mW; RPM: 9000RPM; Bearing Type: Sleeve
R23 = RES_0805_2K: as R4 on sheet 03 POWER
SERVO1 = Servo_Header: Board-To-Board Connector, Vertical, WR-PHD Series, Through Hole, Header, 3 Contacts, 2.54 mm; Manufacturer: Wurth Electronics; Number of Positions: 3; Gender: Male; Connector Type: Male Pin; Pitch: 0.1inch
TP69-TP72 = TP: as TP55 on sheet 03 POWER
U8 = PCA9685PW: as U11 on sheet 02 LEDs

## Sheet 06 Gyro.SchDoc
size 152 x 139 mm
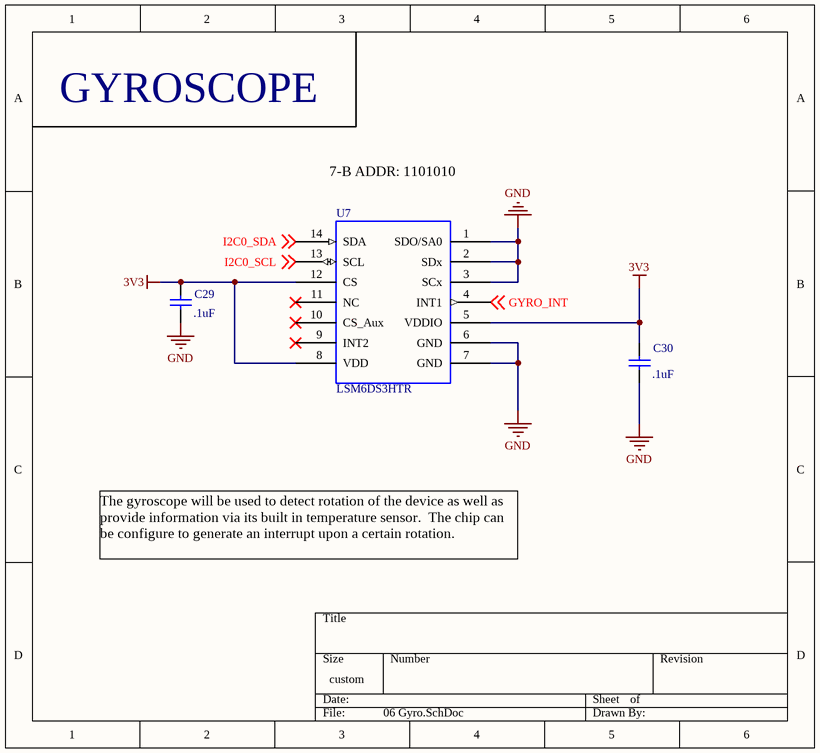
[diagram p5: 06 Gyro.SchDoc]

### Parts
C29  value .1uF  [CAPC2012X135N]  (hidden comment: CAP_0805_.1u_250V)
C30  value .1uF  [CAPC2012X135N]  (hidden comment: CAP_0805_.1u_250V)
U7  LSM6DS3HTR  [PQFN50P300X250X86_HS-15N]

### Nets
3V3: C29.2 C30.2 U7.5(VDDIO) U7.8(VDD) U7.12(CS)
GND: C29.1 C30.1 U7.1(SDO/SA0) U7.2(SDx) U7.3(SCx) U7.6(GND) U7.7(GND)
GYRO_INT: U7.4(INT1) ; off-sheet GYRO_INT
I2C0_SCL: U7.13(SCL) ; off-sheet I2C0_SCL
I2C0_SDA: U7.14(SDA) ; off-sheet I2C0_SDA

Not connected (* = marked no-connect by the designer): U7 9(INT2)* 10(CS_Aux)* 11(NC)*

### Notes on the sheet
- GYROSCOPE
- 7-B ADDR: 1101010
- The gyroscope will be used to detect rotation of the device as well as provide information via its built in temperature sensor.  The chip can be configure to generate an interrupt upon a certain rotation.

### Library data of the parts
C29 C30 = CAP_0805_.1u_250V: as C41 on sheet 02 LEDs
U7 = LSM6DS3HTR: Accelerometer and Gyroscope 14-Pin LGA T/R; Manufacturer: STMicroelectronics

## Sheet 07 Audio.SchDoc
size A
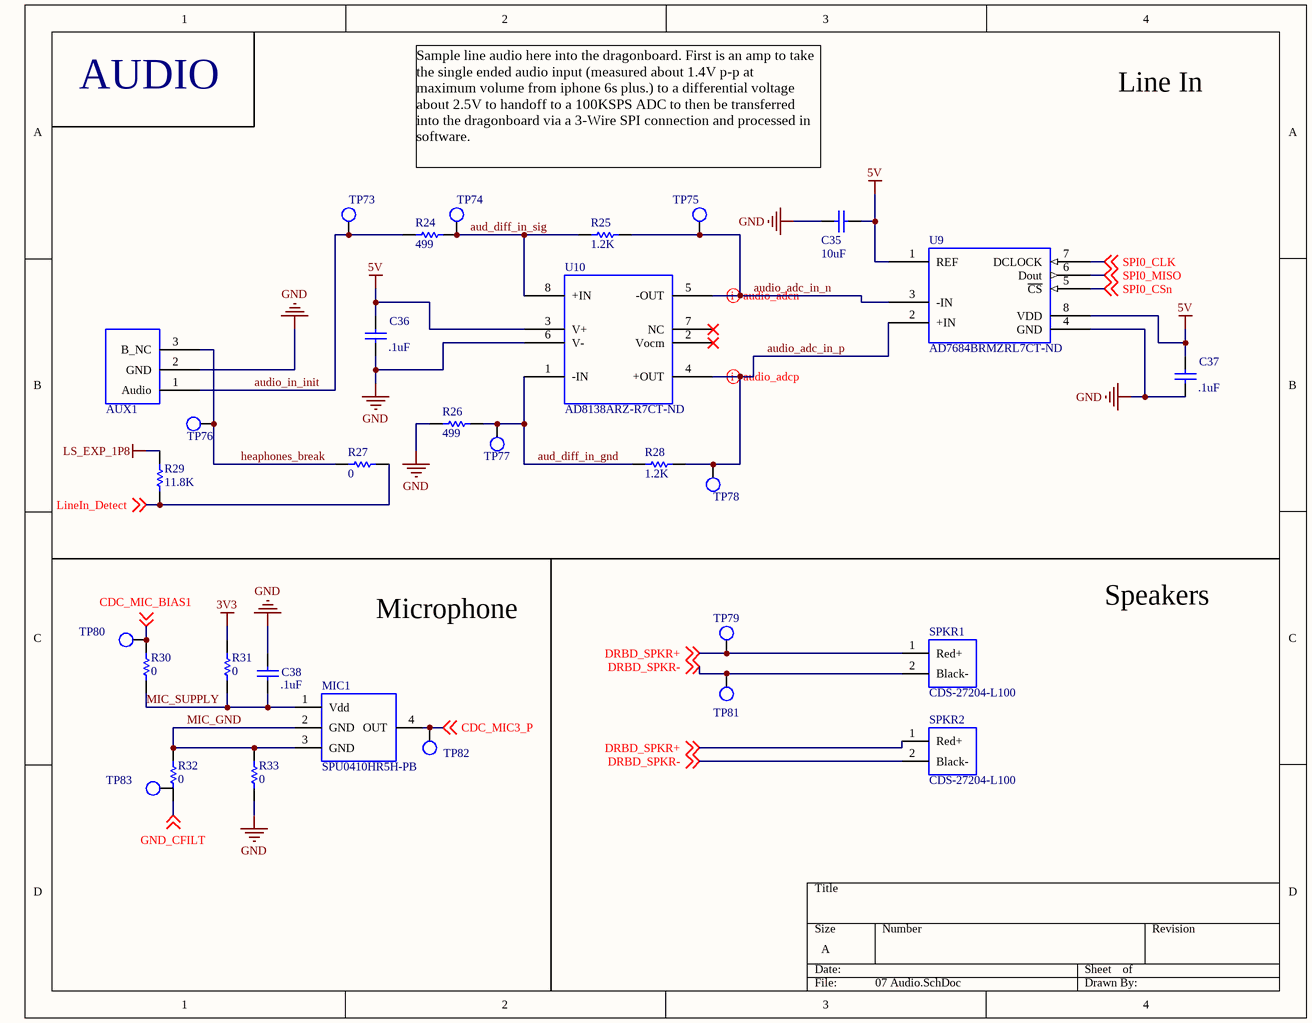
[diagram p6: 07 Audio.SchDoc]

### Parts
AUX1  CP-3523MJCT-ND  [Audio_Conn_Mono]  (value not drawn)
C35  value 10uF  [CAPC2012X135N]  (hidden comment: CAP_0805_10u_16V)
C36  value .1uF  [CAPC2012X135N]  (hidden comment: CAP_0805_.1u_250V)
C37  value .1uF  [CAPC2012X135N]  (hidden comment: CAP_0805_.1u_250V)
C38  value .1uF  [CAPC2012X135N]  (hidden comment: CAP_0805_.1u_250V)
MIC1  SPU0410HR5H-PB  [MIC_FP]
R24  Resistance: 499  [RES0805]  (hidden comment: RES_0805_499)
R25  Resistance: 1.2K  [RES0805]  (hidden comment: RES_0805_1.2K)
R26  Resistance: 499  [RES0805]  (hidden comment: RES_0805_499)
R27  RES_0805_JMP  [RES0805]  (value not drawn)
R28  Resistance: 1.2K  [RES0805]  (hidden comment: RES_0805_1.2K)
R29  RES_0805_11.8K  [RES0805]  (value not drawn)
R30  RES_0805_JMP  [RES0805]  (value not drawn)
R31  RES_0805_JMP  [RES0805]  (value not drawn)
R32  RES_0805_JMP  [RES0805]  (value not drawn)
R33  RES_0805_JMP  [RES0805]  (value not drawn)
SPKR1  CDS-27204-L100  [Speaker_Header]
SPKR2  CDS-27204-L100  [Speaker_Header]
TP73  TP  [TestPoint_1206]  (value not drawn)
TP74  TP  [TestPoint_1206]  (value not drawn)
TP75  TP  [TestPoint_1206]  (value not drawn)
TP76  TP  [TestPoint_1206]  (value not drawn)
TP77  TP  [TestPoint_1206]  (value not drawn)
TP78  TP  [TestPoint_1206]  (value not drawn)
TP79  TP  [TestPoint_1206]  (value not drawn)
TP80  TP  [TestPoint_1206]  (value not drawn)
TP81  TP  [TestPoint_1206]  (value not drawn)
TP82  TP  [TestPoint_1206]  (value not drawn)
TP83  TP  [TestPoint_1206]  (value not drawn)
U9  AD7684BRMZRL7CT-ND  [MSOP8]
U10  AD8138ARZ-R7CT-ND  [SOIC127P600X175-8N]

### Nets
3V3: R31.2
5V: C35.1 C36.2 C37.2 U9.1(REF) U9.8(VDD) U10.3(V+)
GND: AUX1.2(GND) C35.2 C36.1 C37.1 C38.2 R26.1 R33.1 U9.4(GND) U10.6(V-)
LS_EXP_1P8: R29.2
aud_diff_in_gnd: R26.2 R28.1 TP77.1 U10.1(-IN)
aud_diff_in_sig: R24.2 R25.1 TP74.1 U10.8(+IN)
audio_adc_in_n: R25.2 TP75.1 U9.3(-IN) U10.5(-OUT)
audio_adc_in_p: R28.2 TP78.1 U9.2(+IN) U10.4(+OUT)
audio_in_init: AUX1.1(Audio) R24.1 TP73.1
CDC_MIC3_P: MIC1.4(OUT) TP82.1 ; off-sheet CDC_MIC3_P
CDC_MIC_BIAS1: R30.2 TP80.1 ; off-sheet CDC_MIC_BIAS1
DRBD_SPKR+: SPKR1.1(Red+) SPKR2.1(Red+) TP79.1 ; off-sheet DRBD_SPKR+
DRBD_SPKR-: SPKR1.2(Black-) SPKR2.2(Black-) TP81.1 ; off-sheet DRBD_SPKR-
GND_CFILT: R32.1 ; off-sheet GND_CFILT
heaphones_break: AUX1.3(B_NC) R27.1 TP76.1
LineIn_Detect: R27.2 R29.1 ; off-sheet LineIn_Detect
MIC_GND: MIC1.2(GND) MIC1.3(GND) R32.2 R33.2
MIC_SUPPLY: C38.1 MIC1.1(Vdd) R30.1 R31.1
SPI0_CLK: U9.7(DCLOCK) ; off-sheet SPI0_CLK
SPI0_CSn: U9.5(~{CS}) ; off-sheet SPI0_CSn
SPI0_MISO: U9.6(Dout) ; off-sheet SPI0_MISO

Not connected (* = marked no-connect by the designer): TP83 1; U10 2(Vocm)* 7(NC)*

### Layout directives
differential pair: audio_adc_in_n, audio_adc_in_p

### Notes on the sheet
- AUDIO
- Line In
- Sample line audio here into the dragonboard. First is an amp to take the single ended audio input (measured about 1.4V p-p at
  maximum volume from iphone 6s plus.) to a differential voltage about 2.5V to handoff to a 100KSPS ADC to then be transferred into the dragonboard via a 3-Wire SPI connection and processed in software.
- Microphone
- Speakers

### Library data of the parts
AUX1 = CP-3523MJCT-ND: 3.50mm (0.141", 1/8", Mini Plug) - Headphone Phone Jack Mono Connector Solder; Manufacturer: CUI; Manufacturer Part Number: MJ-3523-SMT-TR; Gender: Female; Shielding: Unshielded; Current Rating: 1A
C35 = CAP_0805_10u_16V: as C39 on sheet 02 LEDs
C36-C38 = CAP_0805_.1u_250V: as C41 on sheet 02 LEDs
MIC1 = SPU0410HR5H-PB: MIC MEMS ANALOG OMNI -42DB; Manufacturer: Knowles; Shape: Rectangular; Impedance: 300R; Voltage Rating: 3.6V; Direction: Omnidirectional; Operating Supply Current: 250uA; Signal to Noise Ratio (SNR): 59dB
R24 R26 = RES_0805_499: Res Thick Film 0805 499 Ohm 1% 0.125W(1/8W) ±100ppm/C Molded SMD Automotive T/R; Manufacturer: Stackpole Electronics; Manufacturer Part Number: RMCF0805FT499R; Power Rating: 125mW; Temperature Coefficient: 100ppm/°C
R25 R28 = RES_0805_1.2K: Res Thick Film 0805 1.2K Ohm 5% 0.125W(1/8W) ±200ppm/C Molded SMD Automotive T/R; Manufacturer: Stackpole Electronics; Manufacturer Part Number: RMCF0805JT1K20; Max Power Dissipation: 125mW; Temperature Coefficient: 200ppm/°C
R27 R30-R33 = RES_0805_JMP: RES, THICK FILM, 0R, 0.125W, 0805; Manufacturer: Yageo; Manufacturer Part Number: RC0805JR-070RL; Resistance: 0mR; Tolerance: 5%; Voltage Rating: 150V; Power Rating: 125mW; Temperature Coefficient: 200ppm/°C
R29 = RES_0805_11.8K: as R9 on sheet 03 POWER
SPKR1 SPKR2 = CDS-27204-L100: 4 Ohm Magnetic Speaker 2W 20Hz ~ 20kHz Top Rectangular 93dB; Manufacturer: CUI; Impedance: 4R; Max Power Dissipation: 2.5W
TP73-TP83 = TP: as TP55 on sheet 03 POWER
U9 = AD7684BRMZRL7CT-ND: IC ADC 16BIT 100KSPS DIFF 8MSOP; Manufacturer: Analog Devices; Max Power Dissipation: 6mW; Supply Voltage: 5V; Min Supply Voltage: 2.7V; Max Supply Voltage: 5.5V; Number of Channels: 1; Interface: SPI; Power Consumption: 4mW; Resolution: 16b; Sampling Rate: 100KS/s; Signal to Noise Ratio (SNR): 91dB; Number of Bits: 16; Polarity: Bipolar; Supply Type: Single; Integral Nonlinearity (INL): 3LSB; Input Capacitance: 30pF; Full Scale Error: 15LSB; Min Input Voltage: 500mV
U10 = AD8138ARZ-R7CT-ND: SP Amp Differential ADC Driver Single ±5.5V/11V 8-Pin SOIC N T/R; Manufacturer: Analog Devices; Min Supply Voltage: 2.7V; Max Supply Voltage: 11V; Min Dual Supply Voltage: 1.4V; Max Dual Supply Voltage: 5.5V; Common Mode Rejection Ratio: 70dB; Number of Channels: 1; Bandwidth: 320MHz; Slew Rate: 1150V/µs; Nominal Supply Current: 20mA; Max Power Dissipation: 550mW; Input Offset Voltage (Vos): 1mV; Input Bias Current: 7uA; Voltage Gain: 0.028dB; Input Resistance: 6MR

## Sheet 08 Camera.SchDoc
size 177 x 152 mm
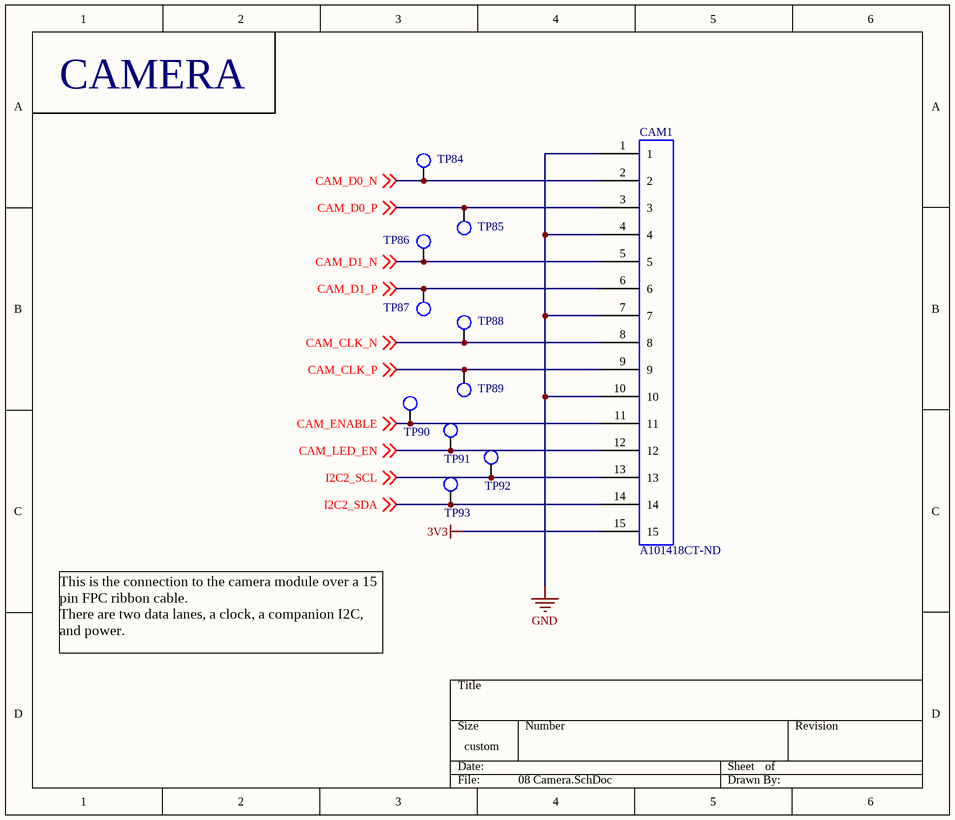
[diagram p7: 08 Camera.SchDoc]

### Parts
CAM1  A101418CT-ND  [ZIF_15pin]
TP84  TP  [TestPoint_1206]  (value not drawn)
TP85  TP  [TestPoint_1206]  (value not drawn)
TP86  TP  [TestPoint_1206]  (value not drawn)
TP87  TP  [TestPoint_1206]  (value not drawn)
TP88  TP  [TestPoint_1206]  (value not drawn)
TP89  TP  [TestPoint_1206]  (value not drawn)
TP90  TP  [TestPoint_1206]  (value not drawn)
TP91  TP  [TestPoint_1206]  (value not drawn)
TP92  TP  [TestPoint_1206]  (value not drawn)
TP93  TP  [TestPoint_1206]  (value not drawn)

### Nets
3V3: CAM1.15
GND: CAM1.1 CAM1.4 CAM1.7 CAM1.10
CAM_CLK_N: CAM1.8 TP88.1 ; off-sheet CAM_CLK_N
CAM_CLK_P: CAM1.9 TP89.1 ; off-sheet CAM_CLK_P
CAM_D0_N: CAM1.2 TP84.1 ; off-sheet CAM_D0_N
CAM_D0_P: CAM1.3 TP85.1 ; off-sheet CAM_D0_P
CAM_D1_N: CAM1.5 TP86.1 ; off-sheet CAM_D1_N
CAM_D1_P: CAM1.6 TP87.1 ; off-sheet CAM_D1_P
CAM_ENABLE: CAM1.11 TP90.1 ; off-sheet CAM_ENABLE
CAM_LED_EN: CAM1.12 TP91.1 ; off-sheet CAM_LED_EN
I2C2_SCL: CAM1.13 TP92.1 ; off-sheet I2C2_SCL
I2C2_SDA: CAM1.14 TP93.1 ; off-sheet I2C2_SDA

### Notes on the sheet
- CAMERA
- This is the connection to the camera module over a 15 pin FPC ribbon cable.
  There are two data lanes, a clock, a companion I2C, and power.

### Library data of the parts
CAM1 = A101418CT-ND: CONN FPC VERT 15POS 1.00MM SMD; Manufacturer: TE Connectivity; Manufacturer Part Number: 1-1734248-5; Current Rating: 1A; Voltage Rating: 125V; Gender: Receptacle; Number of Positions: 15; Shielding: Unshielded; Connector Type: Connector,Receptacle,Socket; Wire/Cable Type: Flat Flex; Connector System: Flex-to-Board; Mating Alignment: Yes (With); PCB Mount Alignment: No (Without); PCB Mount Retention: With; PCB Mounting Orientation: Vertical; Pitch: 0.039inch
TP84-TP93 = TP: as TP55 on sheet 03 POWER

## Sheet 09 LEDs(2).SchDoc
size A
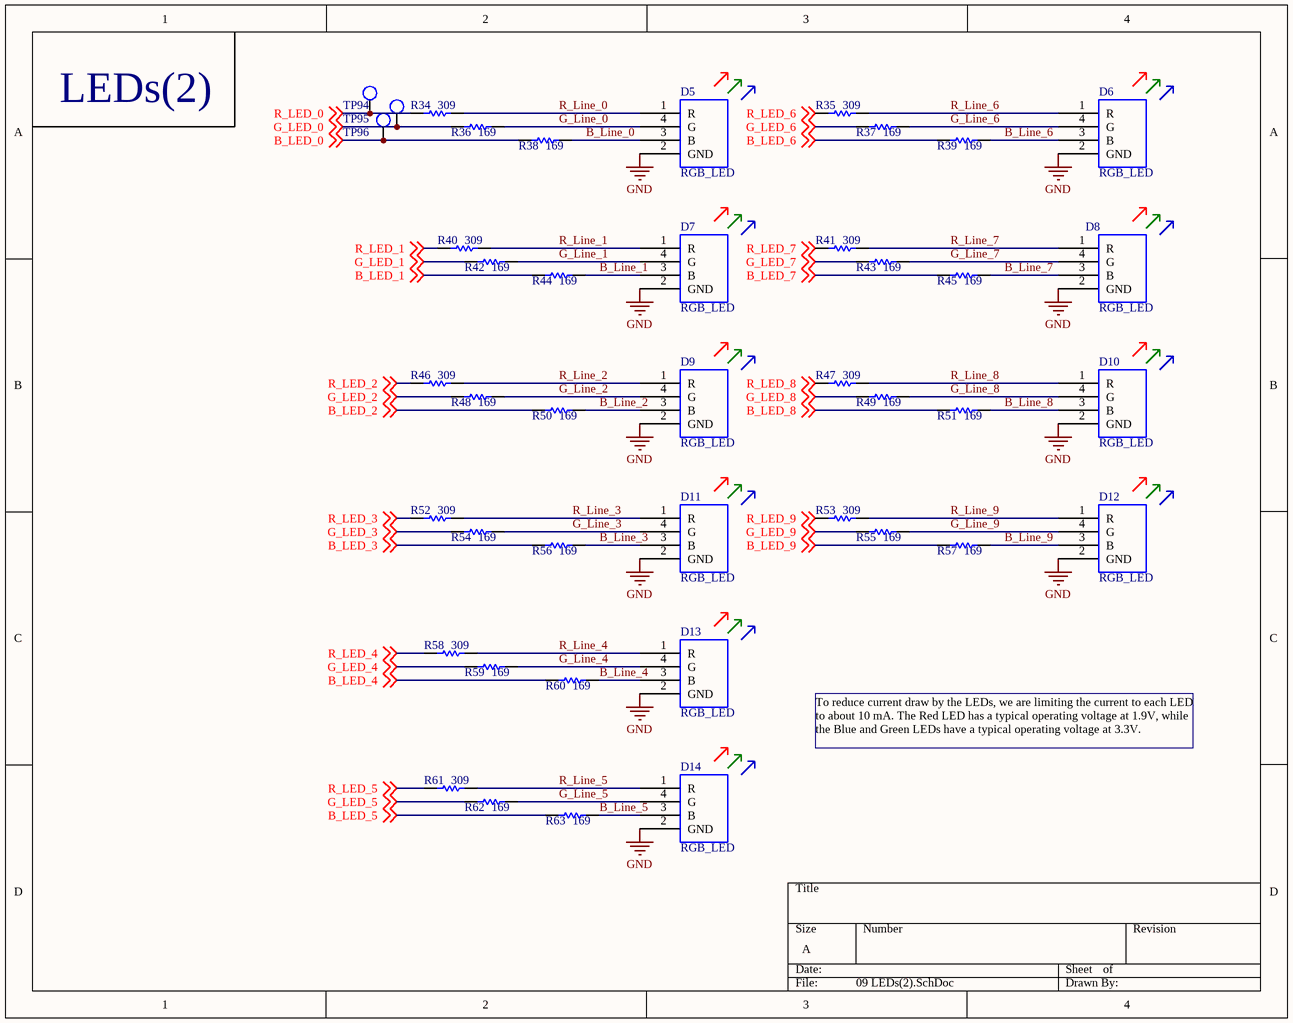
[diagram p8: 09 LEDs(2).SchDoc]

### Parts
D5  RGB_LED  [RGB_LED]
D6  RGB_LED  [RGB_LED]
D7  RGB_LED  [RGB_LED]
D8  RGB_LED  [RGB_LED]
D9  RGB_LED  [RGB_LED]
D10  RGB_LED  [RGB_LED]
D11  RGB_LED  [RGB_LED]
D12  RGB_LED  [RGB_LED]
D13  RGB_LED  [RGB_LED]
D14  RGB_LED  [RGB_LED]
R34  RES_0805_309  [RES0805]  (value not drawn)
R35  RES_0805_309  [RES0805]  (value not drawn)
R36  169 Ohm  [RES0805]  (value not drawn)
R37  169 Ohm  [RES0805]  (value not drawn)
R38  169 Ohm  [RES0805]  (value not drawn)
R39  169 Ohm  [RES0805]  (value not drawn)
R40  RES_0805_309  [RES0805]  (value not drawn)
R41  RES_0805_309  [RES0805]  (value not drawn)
R42  169 Ohm  [RES0805]  (value not drawn)
R43  169 Ohm  [RES0805]  (value not drawn)
R44  169 Ohm  [RES0805]  (value not drawn)
R45  169 Ohm  [RES0805]  (value not drawn)
R46  RES_0805_309  [RES0805]  (value not drawn)
R47  RES_0805_309  [RES0805]  (value not drawn)
R48  169 Ohm  [RES0805]  (value not drawn)
R49  169 Ohm  [RES0805]  (value not drawn)
R50  169 Ohm  [RES0805]  (value not drawn)
R51  169 Ohm  [RES0805]  (value not drawn)
R52  RES_0805_309  [RES0805]  (value not drawn)
R53  RES_0805_309  [RES0805]  (value not drawn)
R54  169 Ohm  [RES0805]  (value not drawn)
R55  169 Ohm  [RES0805]  (value not drawn)
R56  169 Ohm  [RES0805]  (value not drawn)
R57  169 Ohm  [RES0805]  (value not drawn)
R58  RES_0805_309  [RES0805]  (value not drawn)
R59  169 Ohm  [RES0805]  (value not drawn)
R60  169 Ohm  [RES0805]  (value not drawn)
R61  RES_0805_309  [RES0805]  (value not drawn)
R62  169 Ohm  [RES0805]  (value not drawn)
R63  169 Ohm  [RES0805]  (value not drawn)
TP94  TP  [TestPoint_1206]  (value not drawn)
TP95  TP  [TestPoint_1206]  (value not drawn)
TP96  TP  [TestPoint_1206]  (value not drawn)

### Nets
GND: D5.2(GND) D6.2(GND) D7.2(GND) D8.2(GND) D9.2(GND) D10.2(GND) D11.2(GND) D12.2(GND) D13.2(GND) D14.2(GND)
B_LED_0: R38.1 TP96.1 ; off-sheet B_LED_0
B_LED_1: R44.1 ; off-sheet B_LED_1
B_LED_2: R50.1 ; off-sheet B_LED_2
B_LED_3: R56.1 ; off-sheet B_LED_3
B_LED_4: R60.1 ; off-sheet B_LED_4
B_LED_5: R63.1 ; off-sheet B_LED_5
B_LED_6: R39.1 ; off-sheet B_LED_6
B_LED_7: R45.1 ; off-sheet B_LED_7
B_LED_8: R51.1 ; off-sheet B_LED_8
B_LED_9: R57.1 ; off-sheet B_LED_9
B_Line_0: D5.3(B) R38.2
B_Line_1: D7.3(B) R44.2
B_Line_2: D9.3(B) R50.2
B_Line_3: D11.3(B) R56.2
B_Line_4: D13.3(B) R60.2
B_Line_5: D14.3(B) R63.2
B_Line_6: D6.3(B) R39.2
B_Line_7: D8.3(B) R45.2
B_Line_8: D10.3(B) R51.2
B_Line_9: D12.3(B) R57.2
G_LED_0: R36.1 TP95.1 ; off-sheet G_LED_0
G_LED_1: R42.1 ; off-sheet G_LED_1
G_LED_2: R48.1 ; off-sheet G_LED_2
G_LED_3: R54.1 ; off-sheet G_LED_3
G_LED_4: R59.1 ; off-sheet G_LED_4
G_LED_5: R62.1 ; off-sheet G_LED_5
G_LED_6: R37.1 ; off-sheet G_LED_6
G_LED_7: R43.1 ; off-sheet G_LED_7
G_LED_8: R49.1 ; off-sheet G_LED_8
G_LED_9: R55.1 ; off-sheet G_LED_9
G_Line_0: D5.4(G) R36.2
G_Line_1: D7.4(G) R42.2
G_Line_2: D9.4(G) R48.2
G_Line_3: D11.4(G) R54.2
G_Line_4: D13.4(G) R59.2
G_Line_5: D14.4(G) R62.2
G_Line_6: D6.4(G) R37.2
G_Line_7: D8.4(G) R43.2
G_Line_8: D10.4(G) R49.2
G_Line_9: D12.4(G) R55.2
R_LED_0: R34.1 TP94.1 ; off-sheet R_LED_0
R_LED_1: R40.1 ; off-sheet R_LED_1
R_LED_2: R46.1 ; off-sheet R_LED_2
R_LED_3: R52.1 ; off-sheet R_LED_3
R_LED_4: R58.1 ; off-sheet R_LED_4
R_LED_5: R61.1 ; off-sheet R_LED_5
R_LED_6: R35.1 ; off-sheet R_LED_6
R_LED_7: R41.1 ; off-sheet R_LED_7
R_LED_8: R47.1 ; off-sheet R_LED_8
R_LED_9: R53.1 ; off-sheet R_LED_9
R_Line_0: D5.1(R) R34.2
R_Line_1: D7.1(R) R40.2
R_Line_2: D9.1(R) R46.2
R_Line_3: D11.1(R) R52.2
R_Line_4: D13.1(R) R58.2
R_Line_5: D14.1(R) R61.2
R_Line_6: D6.1(R) R35.2
R_Line_7: D8.1(R) R41.2
R_Line_8: D10.1(R) R47.2
R_Line_9: D12.1(R) R53.2

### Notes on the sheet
- LEDs(2)
- To reduce current draw by the LEDs, we are limiting the current to each LED to about 10 mA. The Red LED has a typical operating voltage at 1.9V, while the Blue and Green LEDs have a typical operating voltage at 3.3V.

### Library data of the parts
D5-D14 = RGB_LED: WP154A4SUREQBFZGC; Manufacturer: Kingbright; Colour: Blue,Green,Red; Luminous Intensity: 900mcd; Lens Style: Dome,Clear; Forward Current: 20mA; Forward Voltage: 3.3V; Viewing Angle: 50°; Dominant Wavelength: 465nm
R34 R35 R40 R41 R46 R47 R52 R53 R58 R61 = RES_0805_309: RES SMD 309 OHM 1% 1/8W 0805; Manufacturer: Yageo; Manufacturer Part Number: RC0805FR-07309RL; Resistance: 309R; Temperature Coefficient: 100ppm/°C; Power Rating: 125mW; Voltage Rating: 150V
R36-R39 R42-R45 R48-R51 R54-R57 R59 R60 R62 R63 = RES_0805_169: RES SMD 169 OHM 1% 1/8W 0805; Manufacturer: Yageo; Manufacturer Part Number: RC0805FR-07169RL; Resistance: 169R; Temperature Coefficient: 100ppm/°C; Power Rating: 125mW; Voltage Rating: 150V
TP94-TP96 = TP: as TP55 on sheet 03 POWER

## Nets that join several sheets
3V3: 03 POWER (10 pins), 04 DragonBoard_INTF (C2.2 U1.19), 06 Gyro (5 pins), 07 Audio (R31.2), 08 Camera (CAM1.15)
5V: 02 LEDs (15 pins), 03 POWER (14 pins), 04 DragonBoard_INTF (C6.2 U2.19), 05 SERVO_FAN (7 pins), 07 Audio (6 pins)
12V_BATTIN: 03 POWER (19 pins), 04 DragonBoard_INTF (J1.36 J1.38)
GND: 02 LEDs (30 pins), 03 POWER (44 pins), 04 DragonBoard_INTF (31 pins), 05 SERVO_FAN (14 pins), 06 Gyro (7 pins), 07 Audio (9 pins), 08 Camera (CAM1.1 CAM1.4 CAM1.7 CAM1.10), 09 LEDs(2) (10 pins)
LS_EXP_1P8: 03 POWER (R18.2), 04 DragonBoard_INTF (10 pins), 07 Audio (R29.2)
B_LED_0: 02 LEDs (U13.6), 09 LEDs(2) (R38.1 TP96.1)
B_LED_1: 02 LEDs (U13.7), 09 LEDs(2) (R44.1)
B_LED_2: 02 LEDs (U13.8), 09 LEDs(2) (R50.1)
B_LED_3: 02 LEDs (U13.9), 09 LEDs(2) (R56.1)
B_LED_4: 02 LEDs (U13.10), 09 LEDs(2) (R60.1)
B_LED_5: 02 LEDs (U13.11), 09 LEDs(2) (R63.1)
B_LED_6: 02 LEDs (U13.12), 09 LEDs(2) (R39.1)
B_LED_7: 02 LEDs (U13.13), 09 LEDs(2) (R45.1)
B_LED_8: 02 LEDs (U13.15), 09 LEDs(2) (R51.1)
B_LED_9: 02 LEDs (U13.16), 09 LEDs(2) (R57.1)
CAM_CLK_N: 04 DragonBoard_INTF (J2.4), 08 Camera (CAM1.8 TP88.1)
CAM_CLK_P: 04 DragonBoard_INTF (J2.2), 08 Camera (CAM1.9 TP89.1)
CAM_D0_N: 04 DragonBoard_INTF (J2.10), 08 Camera (CAM1.2 TP84.1)
CAM_D0_P: 04 DragonBoard_INTF (J2.8), 08 Camera (CAM1.3 TP85.1)
CAM_D1_N: 04 DragonBoard_INTF (J2.16), 08 Camera (CAM1.5 TP86.1)
CAM_D1_P: 04 DragonBoard_INTF (J2.14), 08 Camera (CAM1.6 TP87.1)
CAM_ENABLE: 04 DragonBoard_INTF (TP18.1 U1.14), 08 Camera (CAM1.11 TP90.1)
CAM_LED_EN: 04 DragonBoard_INTF (TP16.1 U1.15), 08 Camera (CAM1.12 TP91.1)
CDC_MIC3_P: 04 DragonBoard_INTF (J3.7), 07 Audio (MIC1.4 TP82.1)
CDC_MIC_BIAS1: 04 DragonBoard_INTF (J3.12), 07 Audio (R30.2 TP80.1)
DRBD_SPKR+: 04 DragonBoard_INTF (J3.1), 07 Audio (SPKR1.1 SPKR2.1 TP79.1)
DRBD_SPKR-: 04 DragonBoard_INTF (J3.2), 07 Audio (SPKR1.2 SPKR2.2 TP81.1)
G_LED_0: 02 LEDs (U11.6), 09 LEDs(2) (R36.1 TP95.1)
G_LED_1: 02 LEDs (U11.7), 09 LEDs(2) (R42.1)
G_LED_2: 02 LEDs (U11.8), 09 LEDs(2) (R48.1)
G_LED_3: 02 LEDs (U11.9), 09 LEDs(2) (R54.1)
G_LED_4: 02 LEDs (U11.10), 09 LEDs(2) (R59.1)
G_LED_5: 02 LEDs (U11.11), 09 LEDs(2) (R62.1)
G_LED_6: 02 LEDs (U11.12), 09 LEDs(2) (R37.1)
G_LED_7: 02 LEDs (U11.13), 09 LEDs(2) (R43.1)
G_LED_8: 02 LEDs (U11.15), 09 LEDs(2) (R49.1)
G_LED_9: 02 LEDs (U11.16), 09 LEDs(2) (R55.1)
GND_CFILT: 04 DragonBoard_INTF (J3.5), 07 Audio (R32.1)
GYRO_INT: 04 DragonBoard_INTF (TP20.1 U1.13), 06 Gyro (U7.4)
I2C0_SCL: 04 DragonBoard_INTF (TP7.1 U1.20), 06 Gyro (U7.13)
I2C0_SDA: 04 DragonBoard_INTF (TP10.1 U1.18), 06 Gyro (U7.14)
I2C1_SCL: 02 LEDs (U11.26 U12.26 U13.26), 04 DragonBoard_INTF (TP35.1 U2.20), 05 SERVO_FAN (U8.26)
I2C1_SDA: 02 LEDs (U11.27 U12.27 U13.27), 04 DragonBoard_INTF (TP37.1 U2.18), 05 SERVO_FAN (U8.27)
I2C2_SCL: 04 DragonBoard_INTF (TP11.1 U1.17), 08 Camera (CAM1.13 TP92.1)
I2C2_SDA: 04 DragonBoard_INTF (TP14.1 U1.16), 08 Camera (CAM1.14 TP93.1)
LineIn_Detect: 04 DragonBoard_INTF (J1.23), 07 Audio (R27.2 R29.1)
R_LED_0: 02 LEDs (U12.6), 09 LEDs(2) (R34.1 TP94.1)
R_LED_1: 02 LEDs (U12.7), 09 LEDs(2) (R40.1)
R_LED_2: 02 LEDs (U12.8), 09 LEDs(2) (R46.1)
R_LED_3: 02 LEDs (U12.9), 09 LEDs(2) (R52.1)
R_LED_4: 02 LEDs (U12.10), 09 LEDs(2) (R58.1)
R_LED_5: 02 LEDs (U12.11), 09 LEDs(2) (R61.1)
R_LED_6: 02 LEDs (U12.12), 09 LEDs(2) (R35.1)
R_LED_7: 02 LEDs (U12.13), 09 LEDs(2) (R41.1)
R_LED_8: 02 LEDs (U12.15), 09 LEDs(2) (R47.1)
R_LED_9: 02 LEDs (U12.16), 09 LEDs(2) (R53.1)
SPI0_CLK: 04 DragonBoard_INTF (TP43.1 U2.15), 07 Audio (U9.7)
SPI0_CSn: 04 DragonBoard_INTF (TP47.1 U2.13), 07 Audio (U9.5)
SPI0_MISO: 04 DragonBoard_INTF (TP45.1 U2.14), 07 Audio (U9.6)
